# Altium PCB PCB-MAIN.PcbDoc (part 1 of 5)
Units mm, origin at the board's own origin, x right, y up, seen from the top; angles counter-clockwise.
Board outline 110 x 75 mm, 8 copper layers (F.Cu, In1.Cu, In2.Cu, In3.Cu, In4.Cu, In5.Cu, In6.Cu, B.Cu); 251 components, 185 nets, 1143 pads, 853 vias.
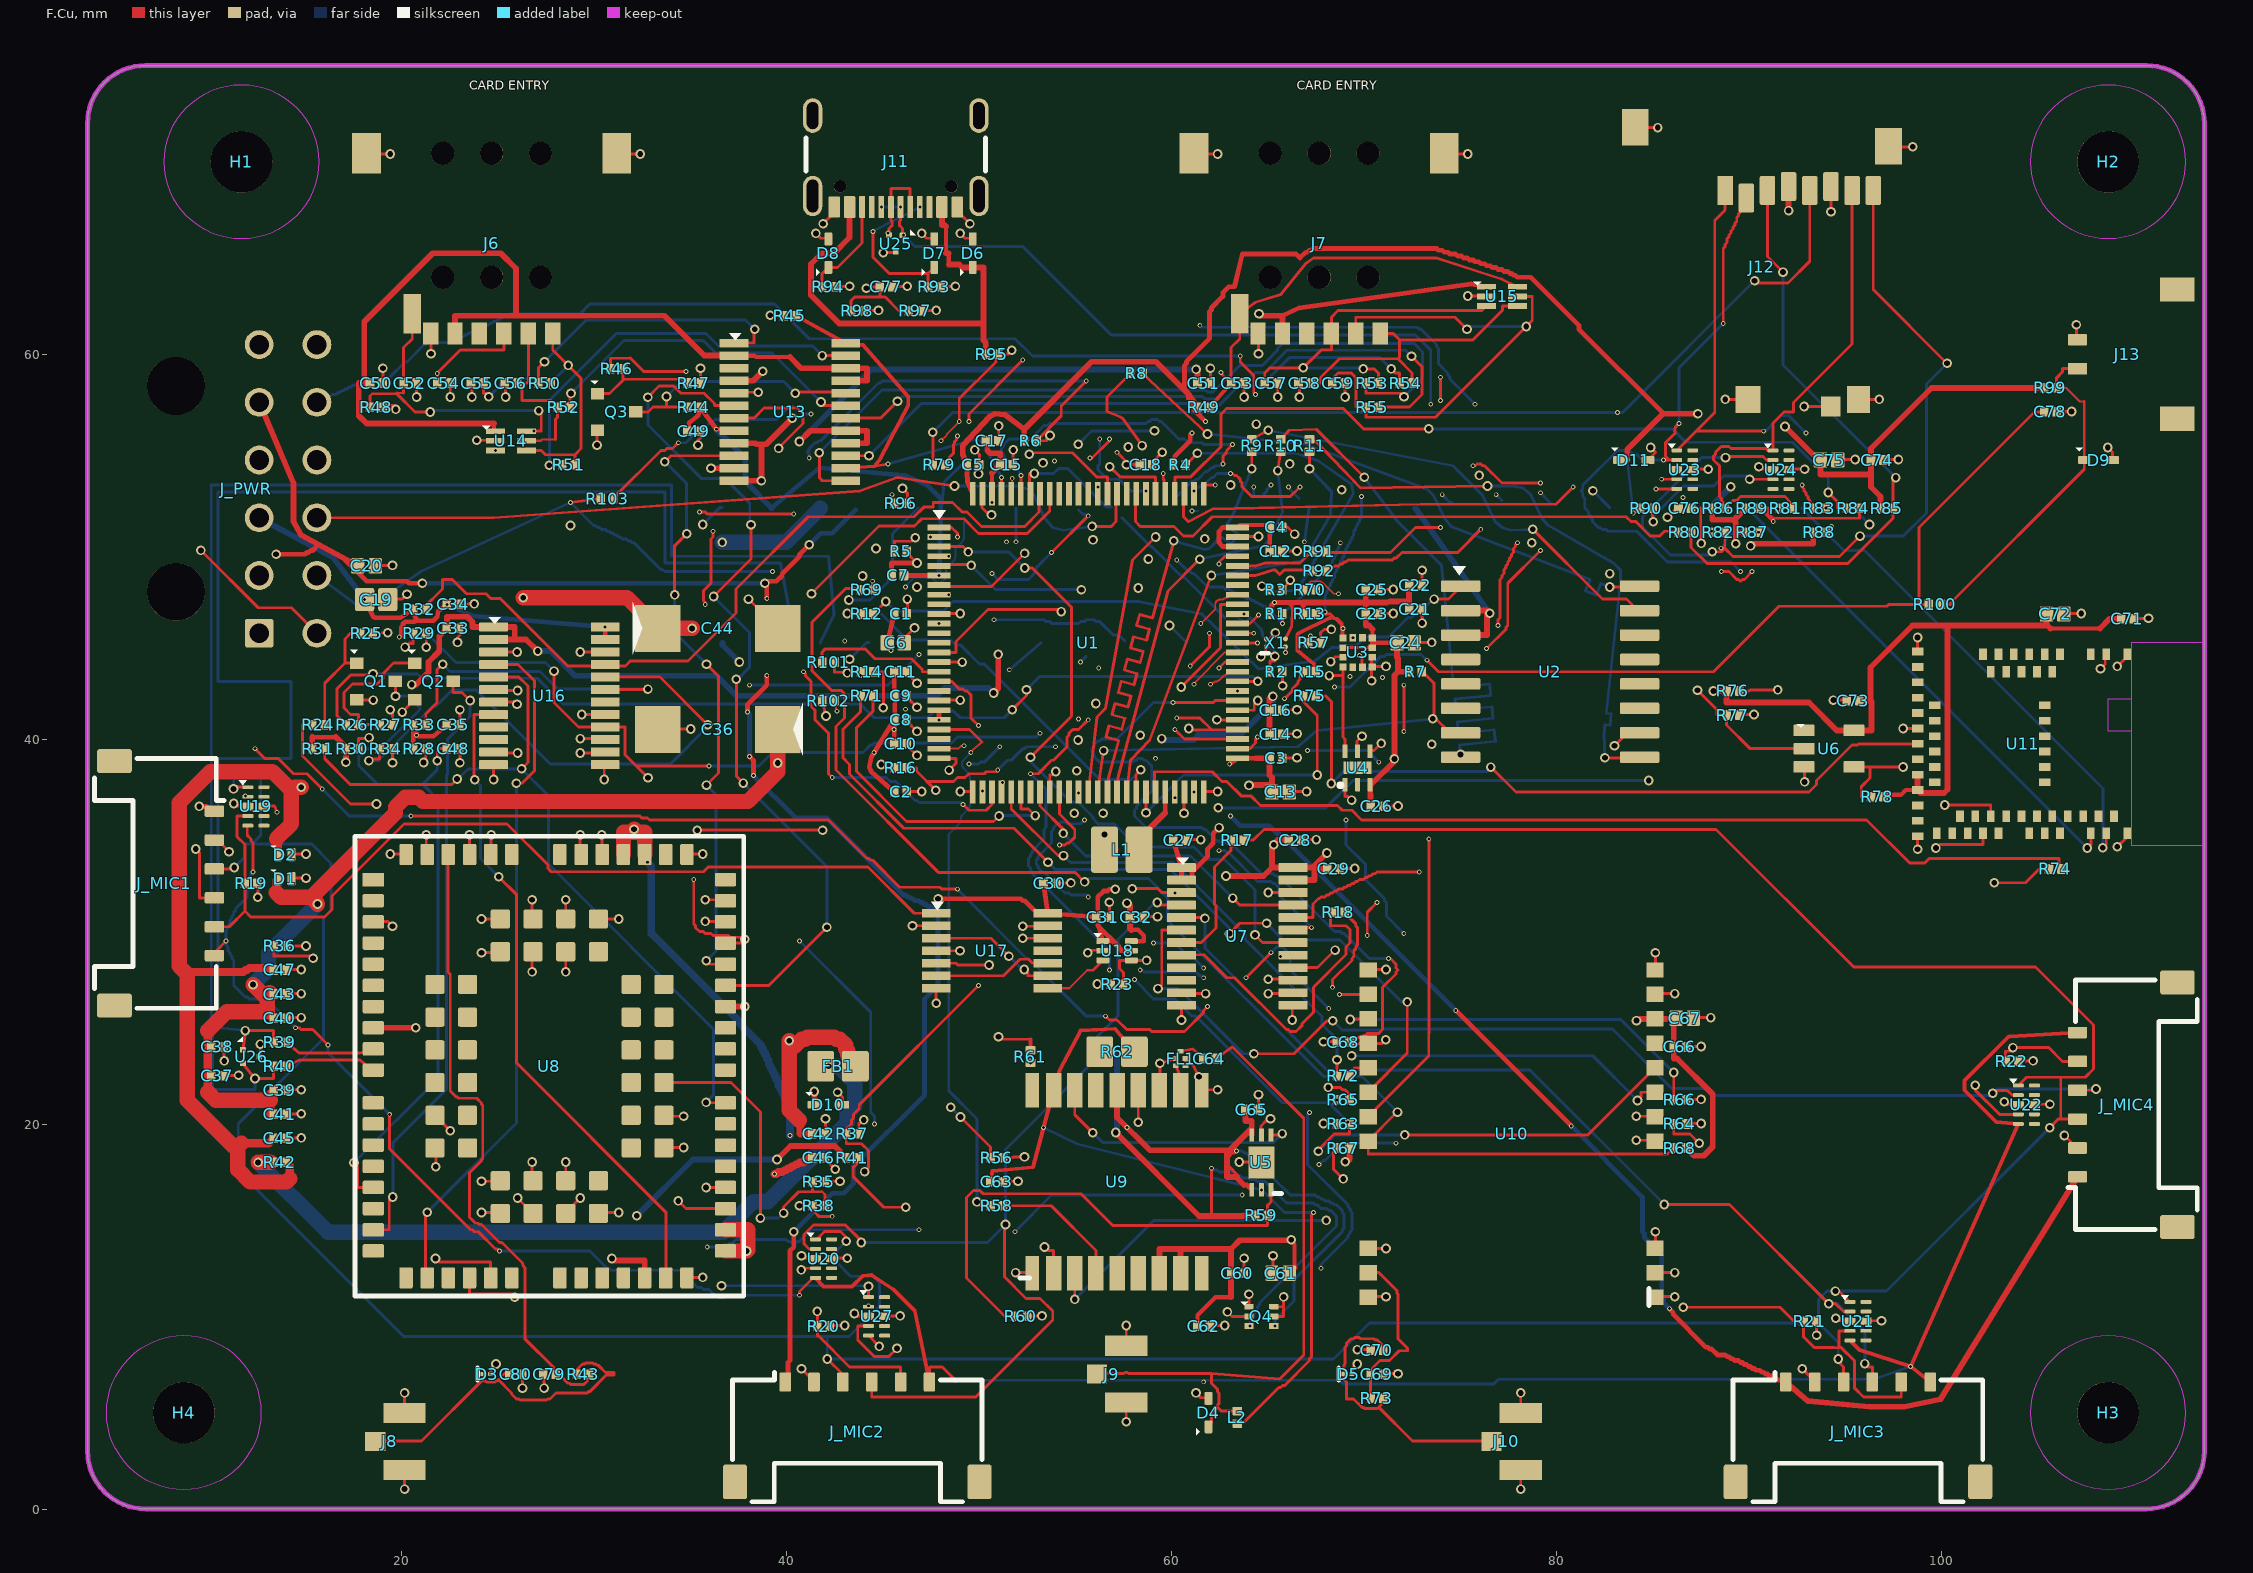
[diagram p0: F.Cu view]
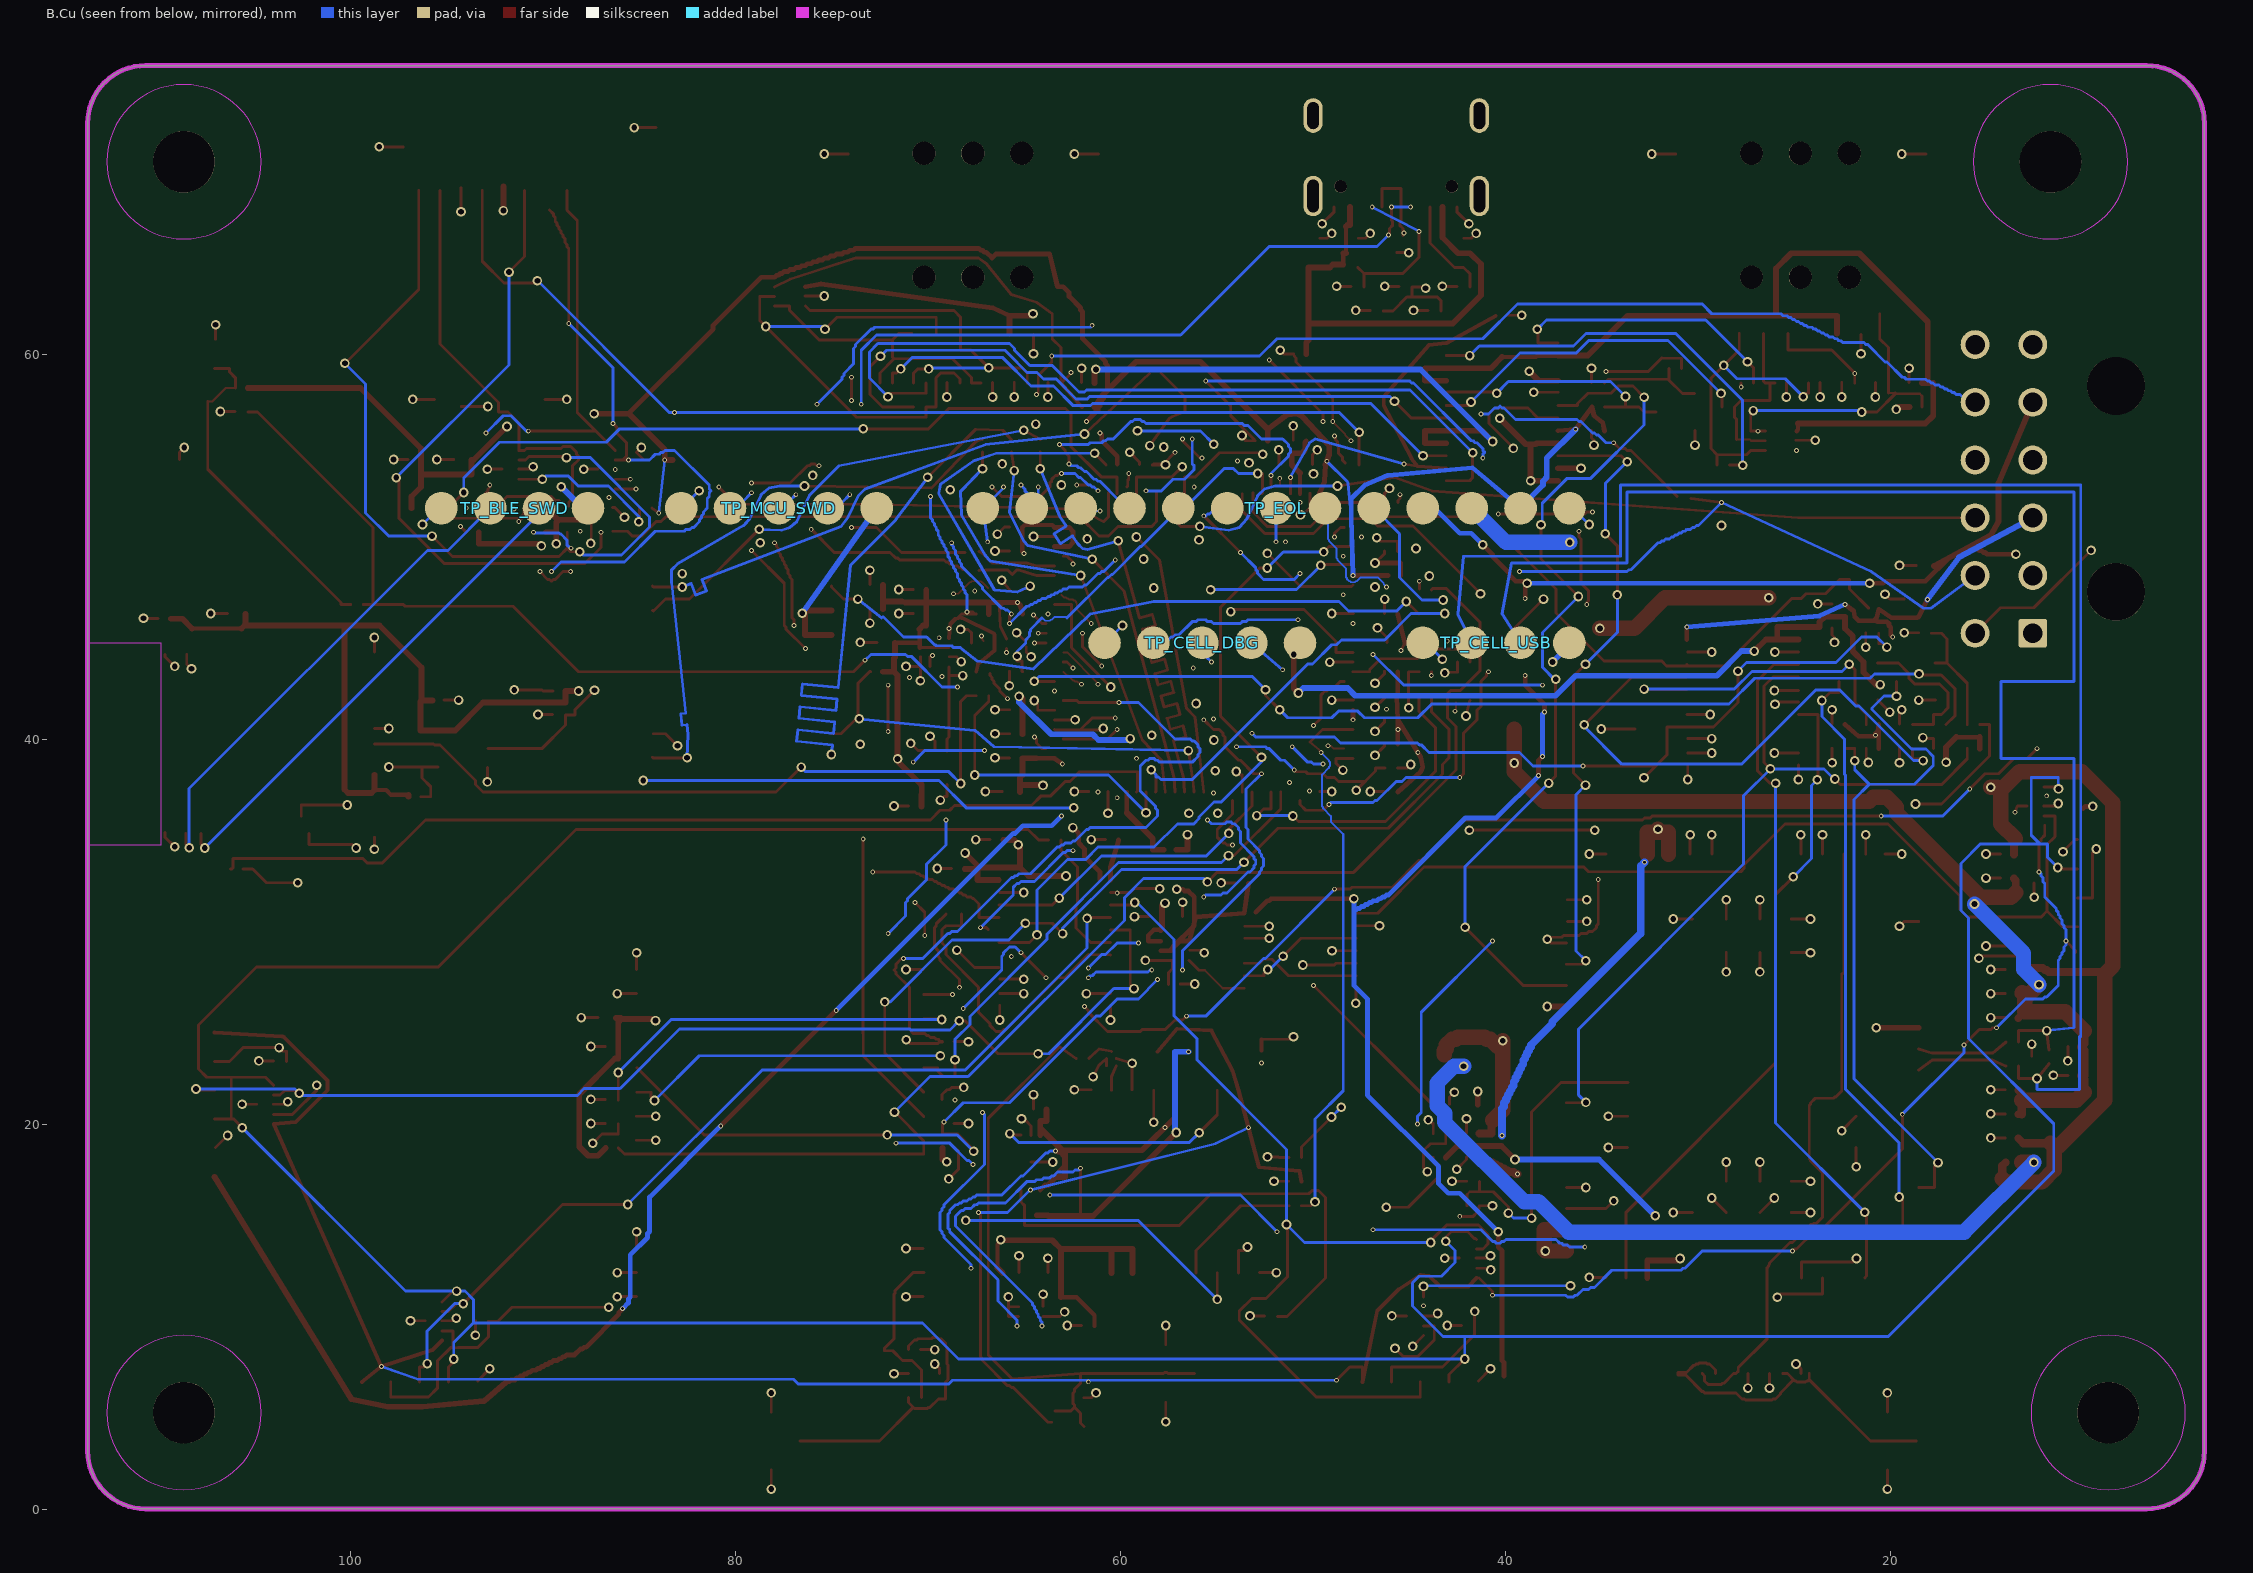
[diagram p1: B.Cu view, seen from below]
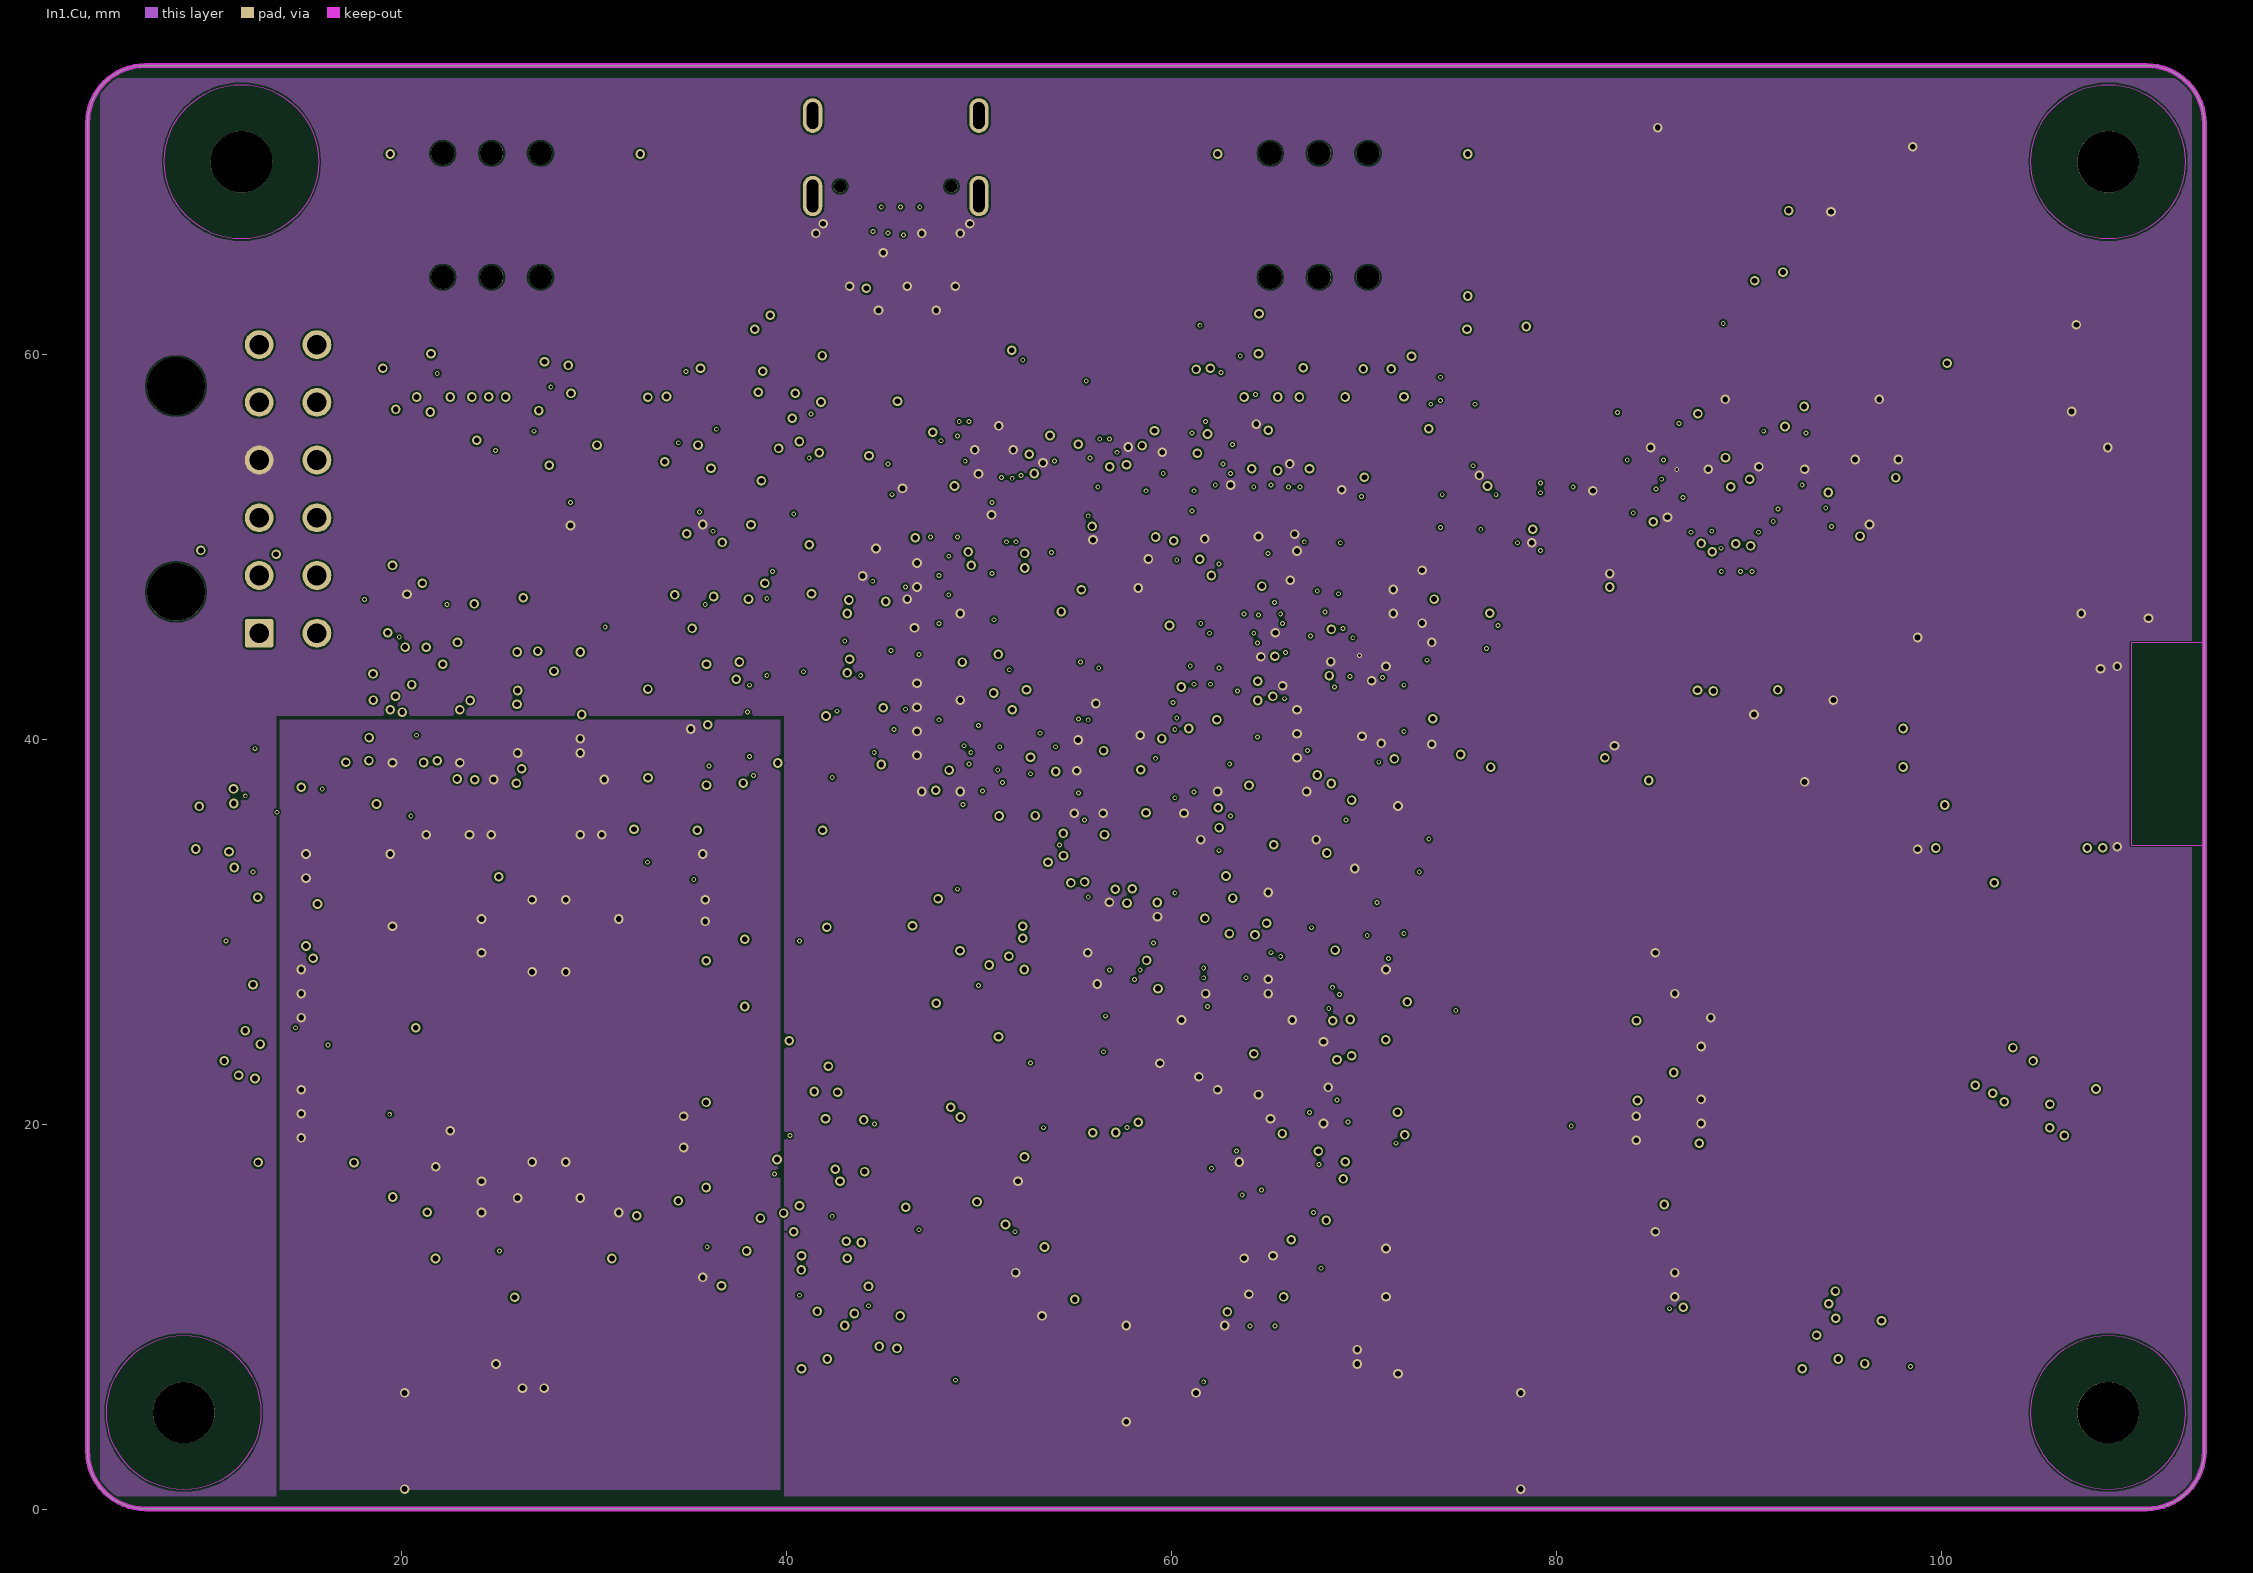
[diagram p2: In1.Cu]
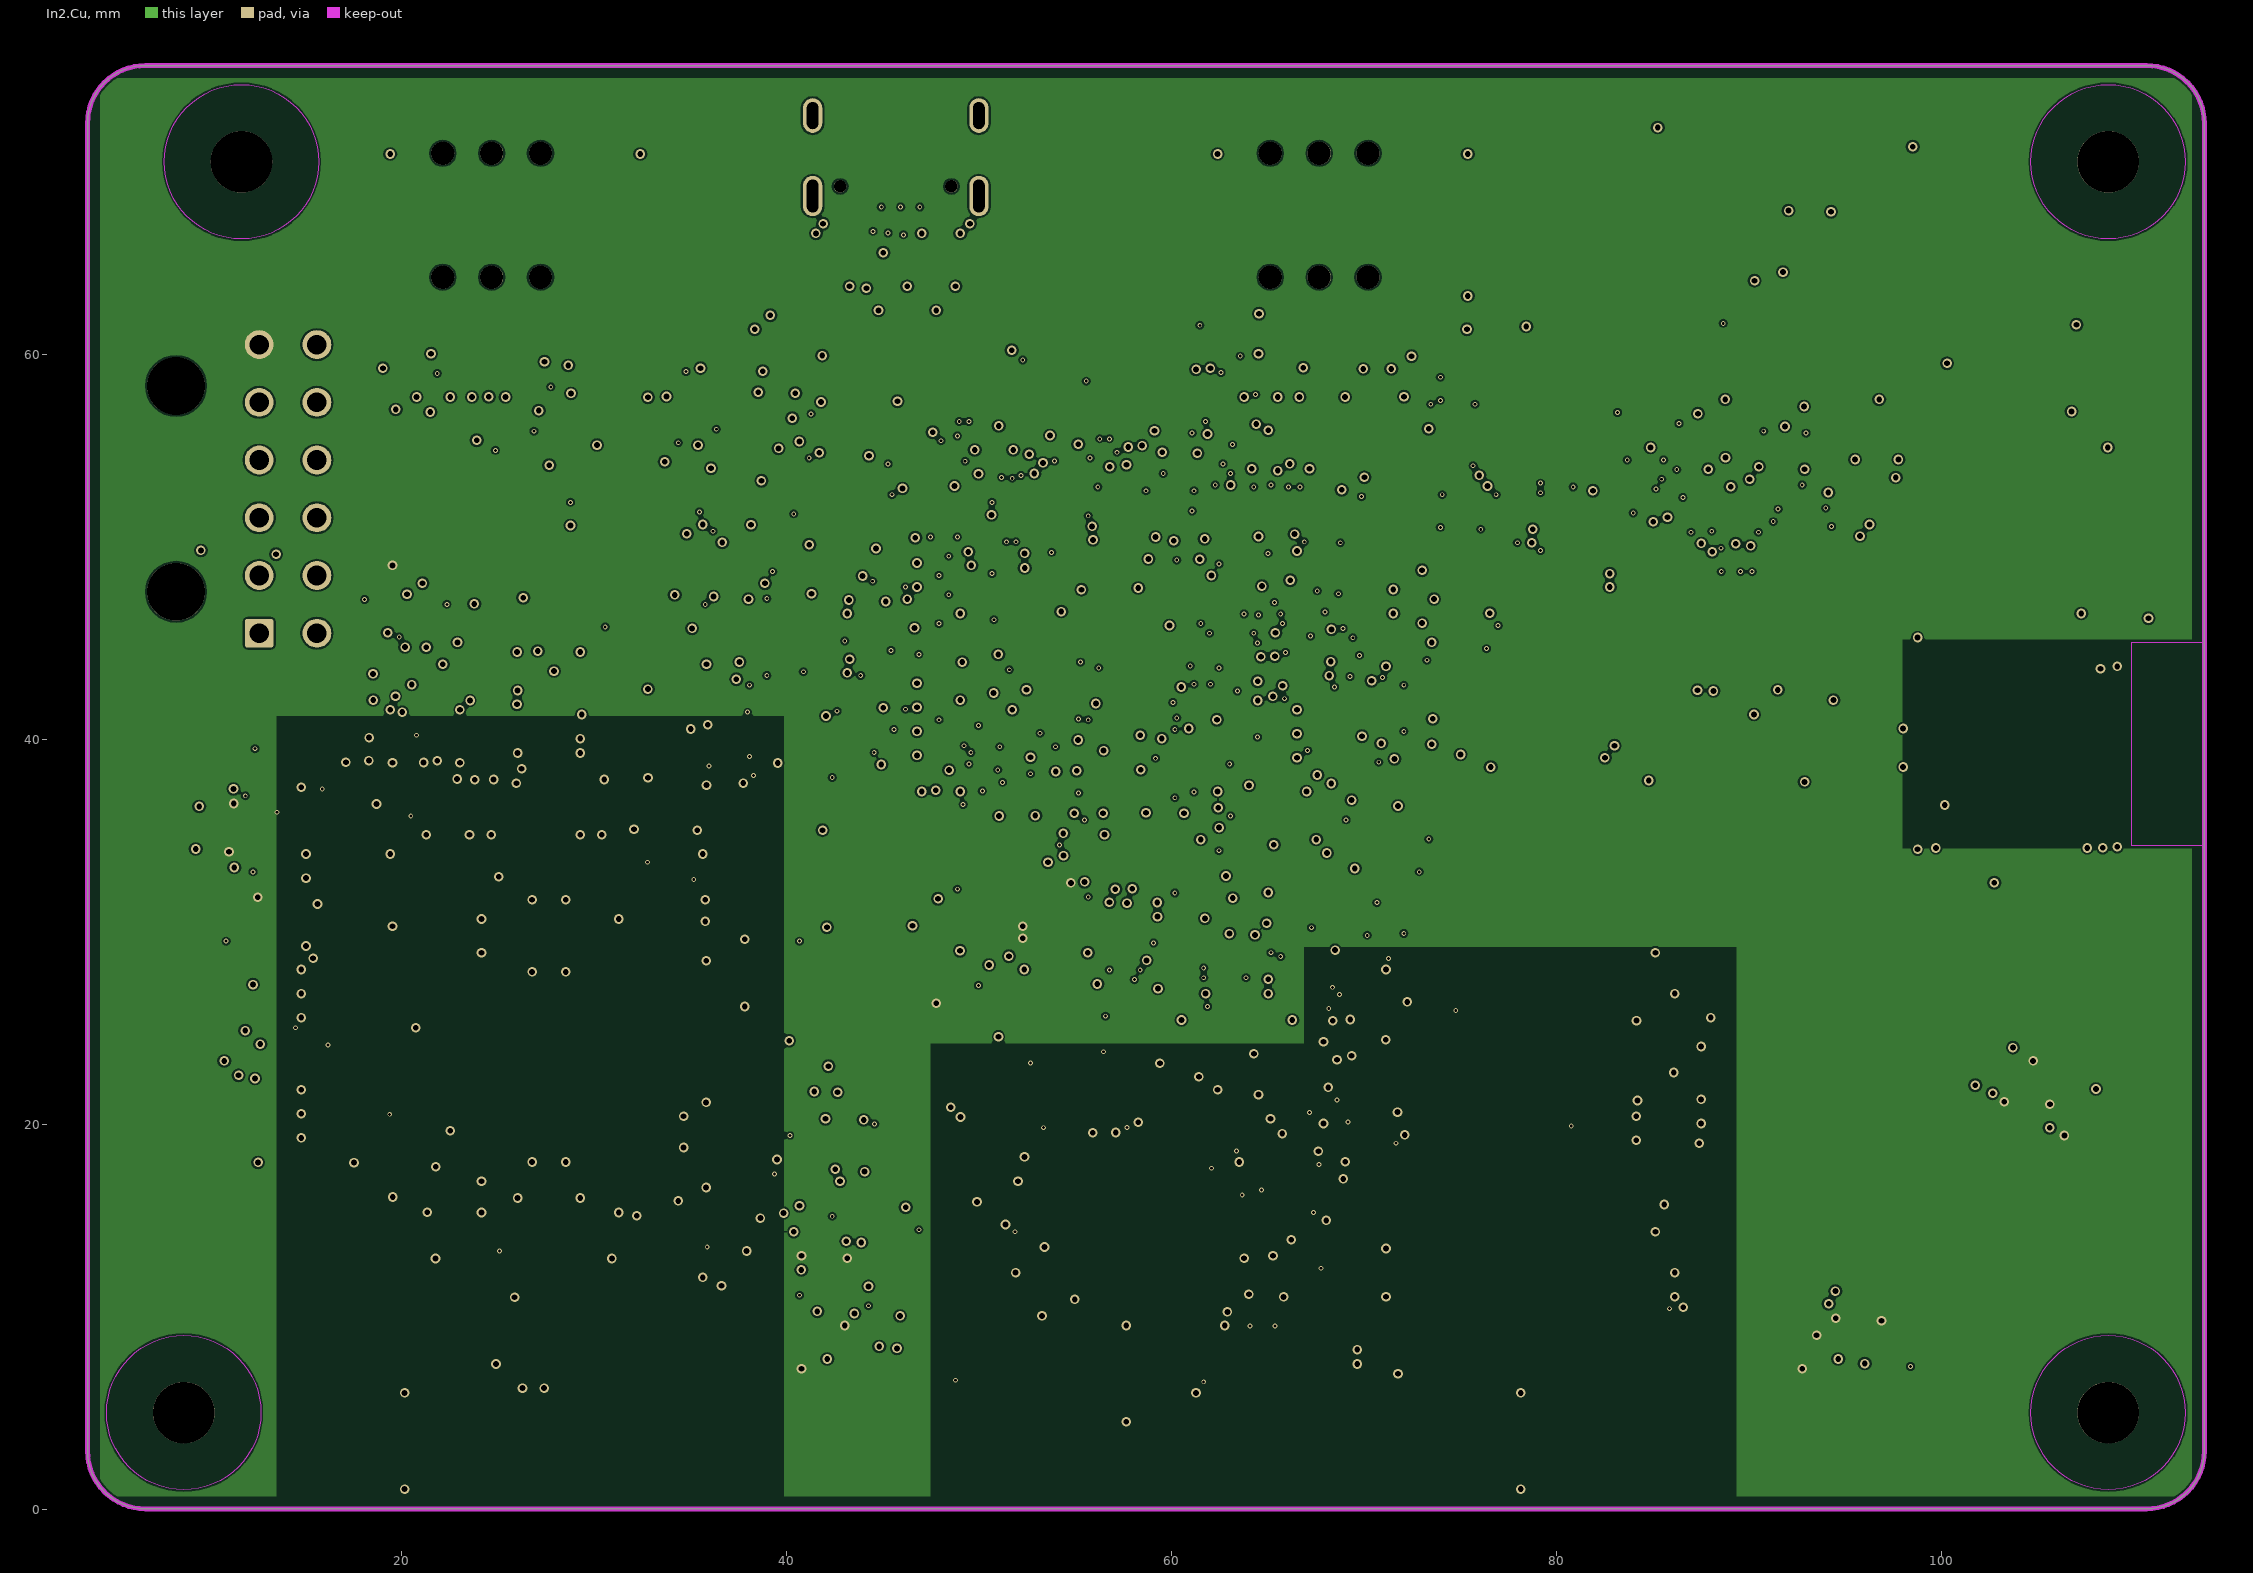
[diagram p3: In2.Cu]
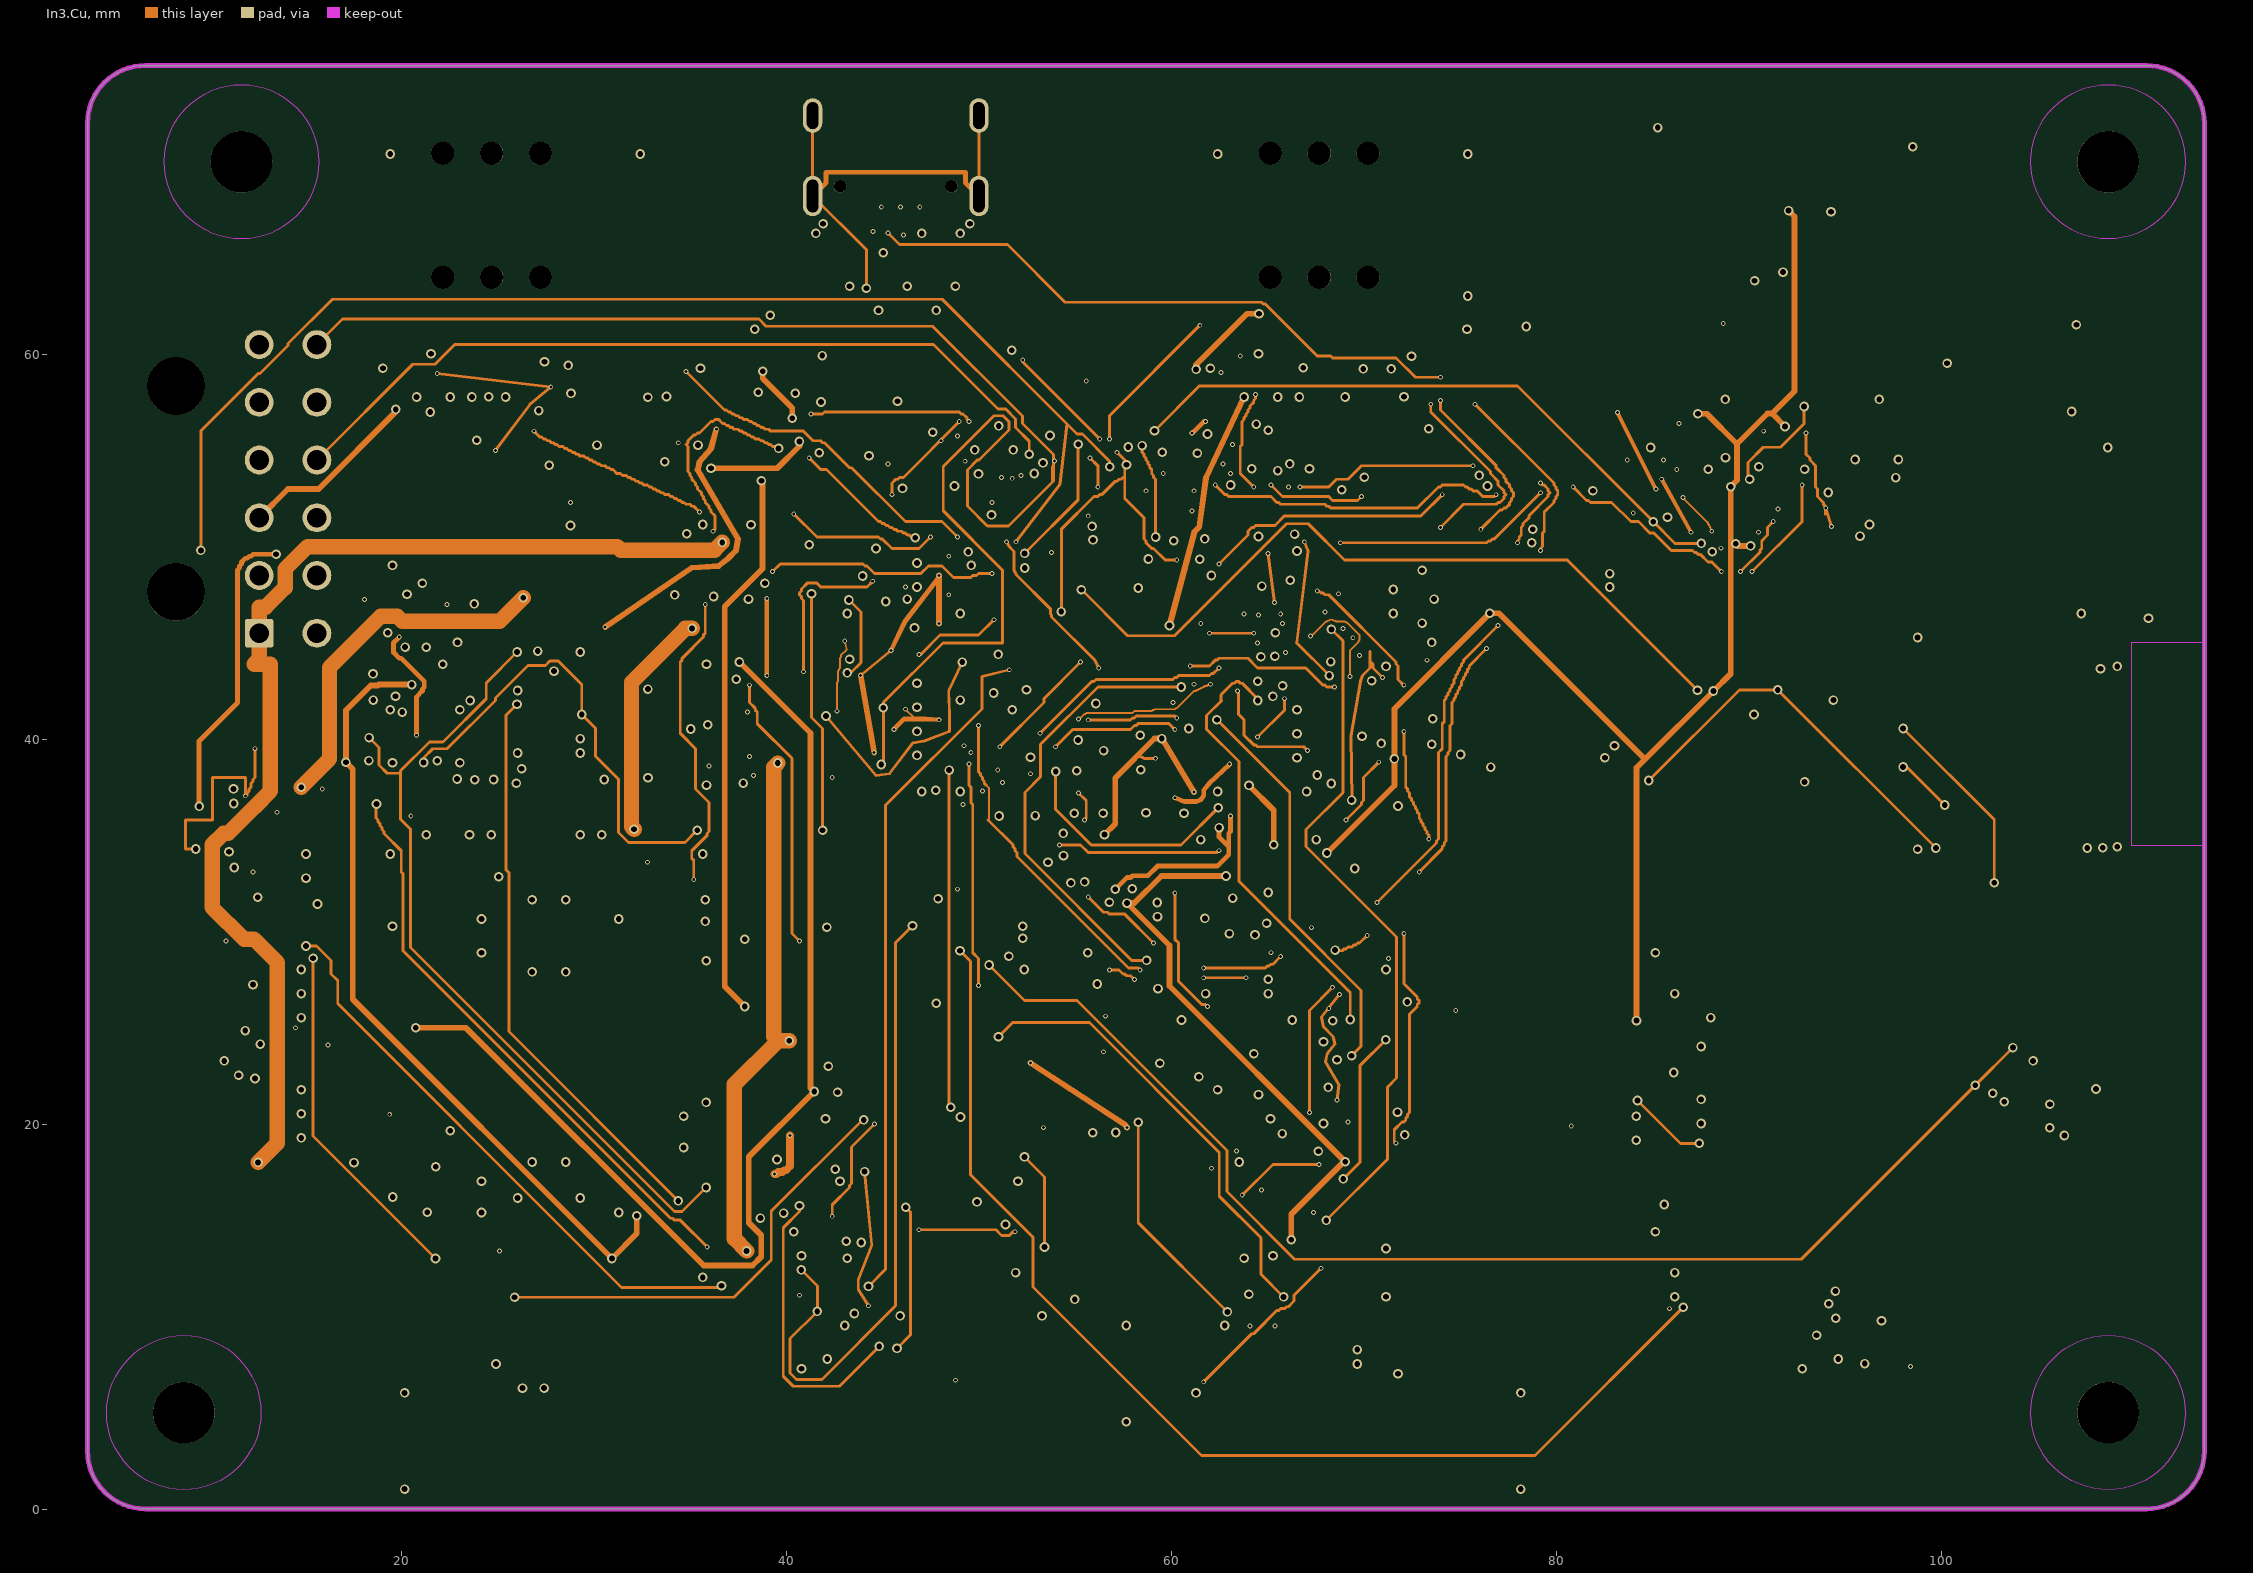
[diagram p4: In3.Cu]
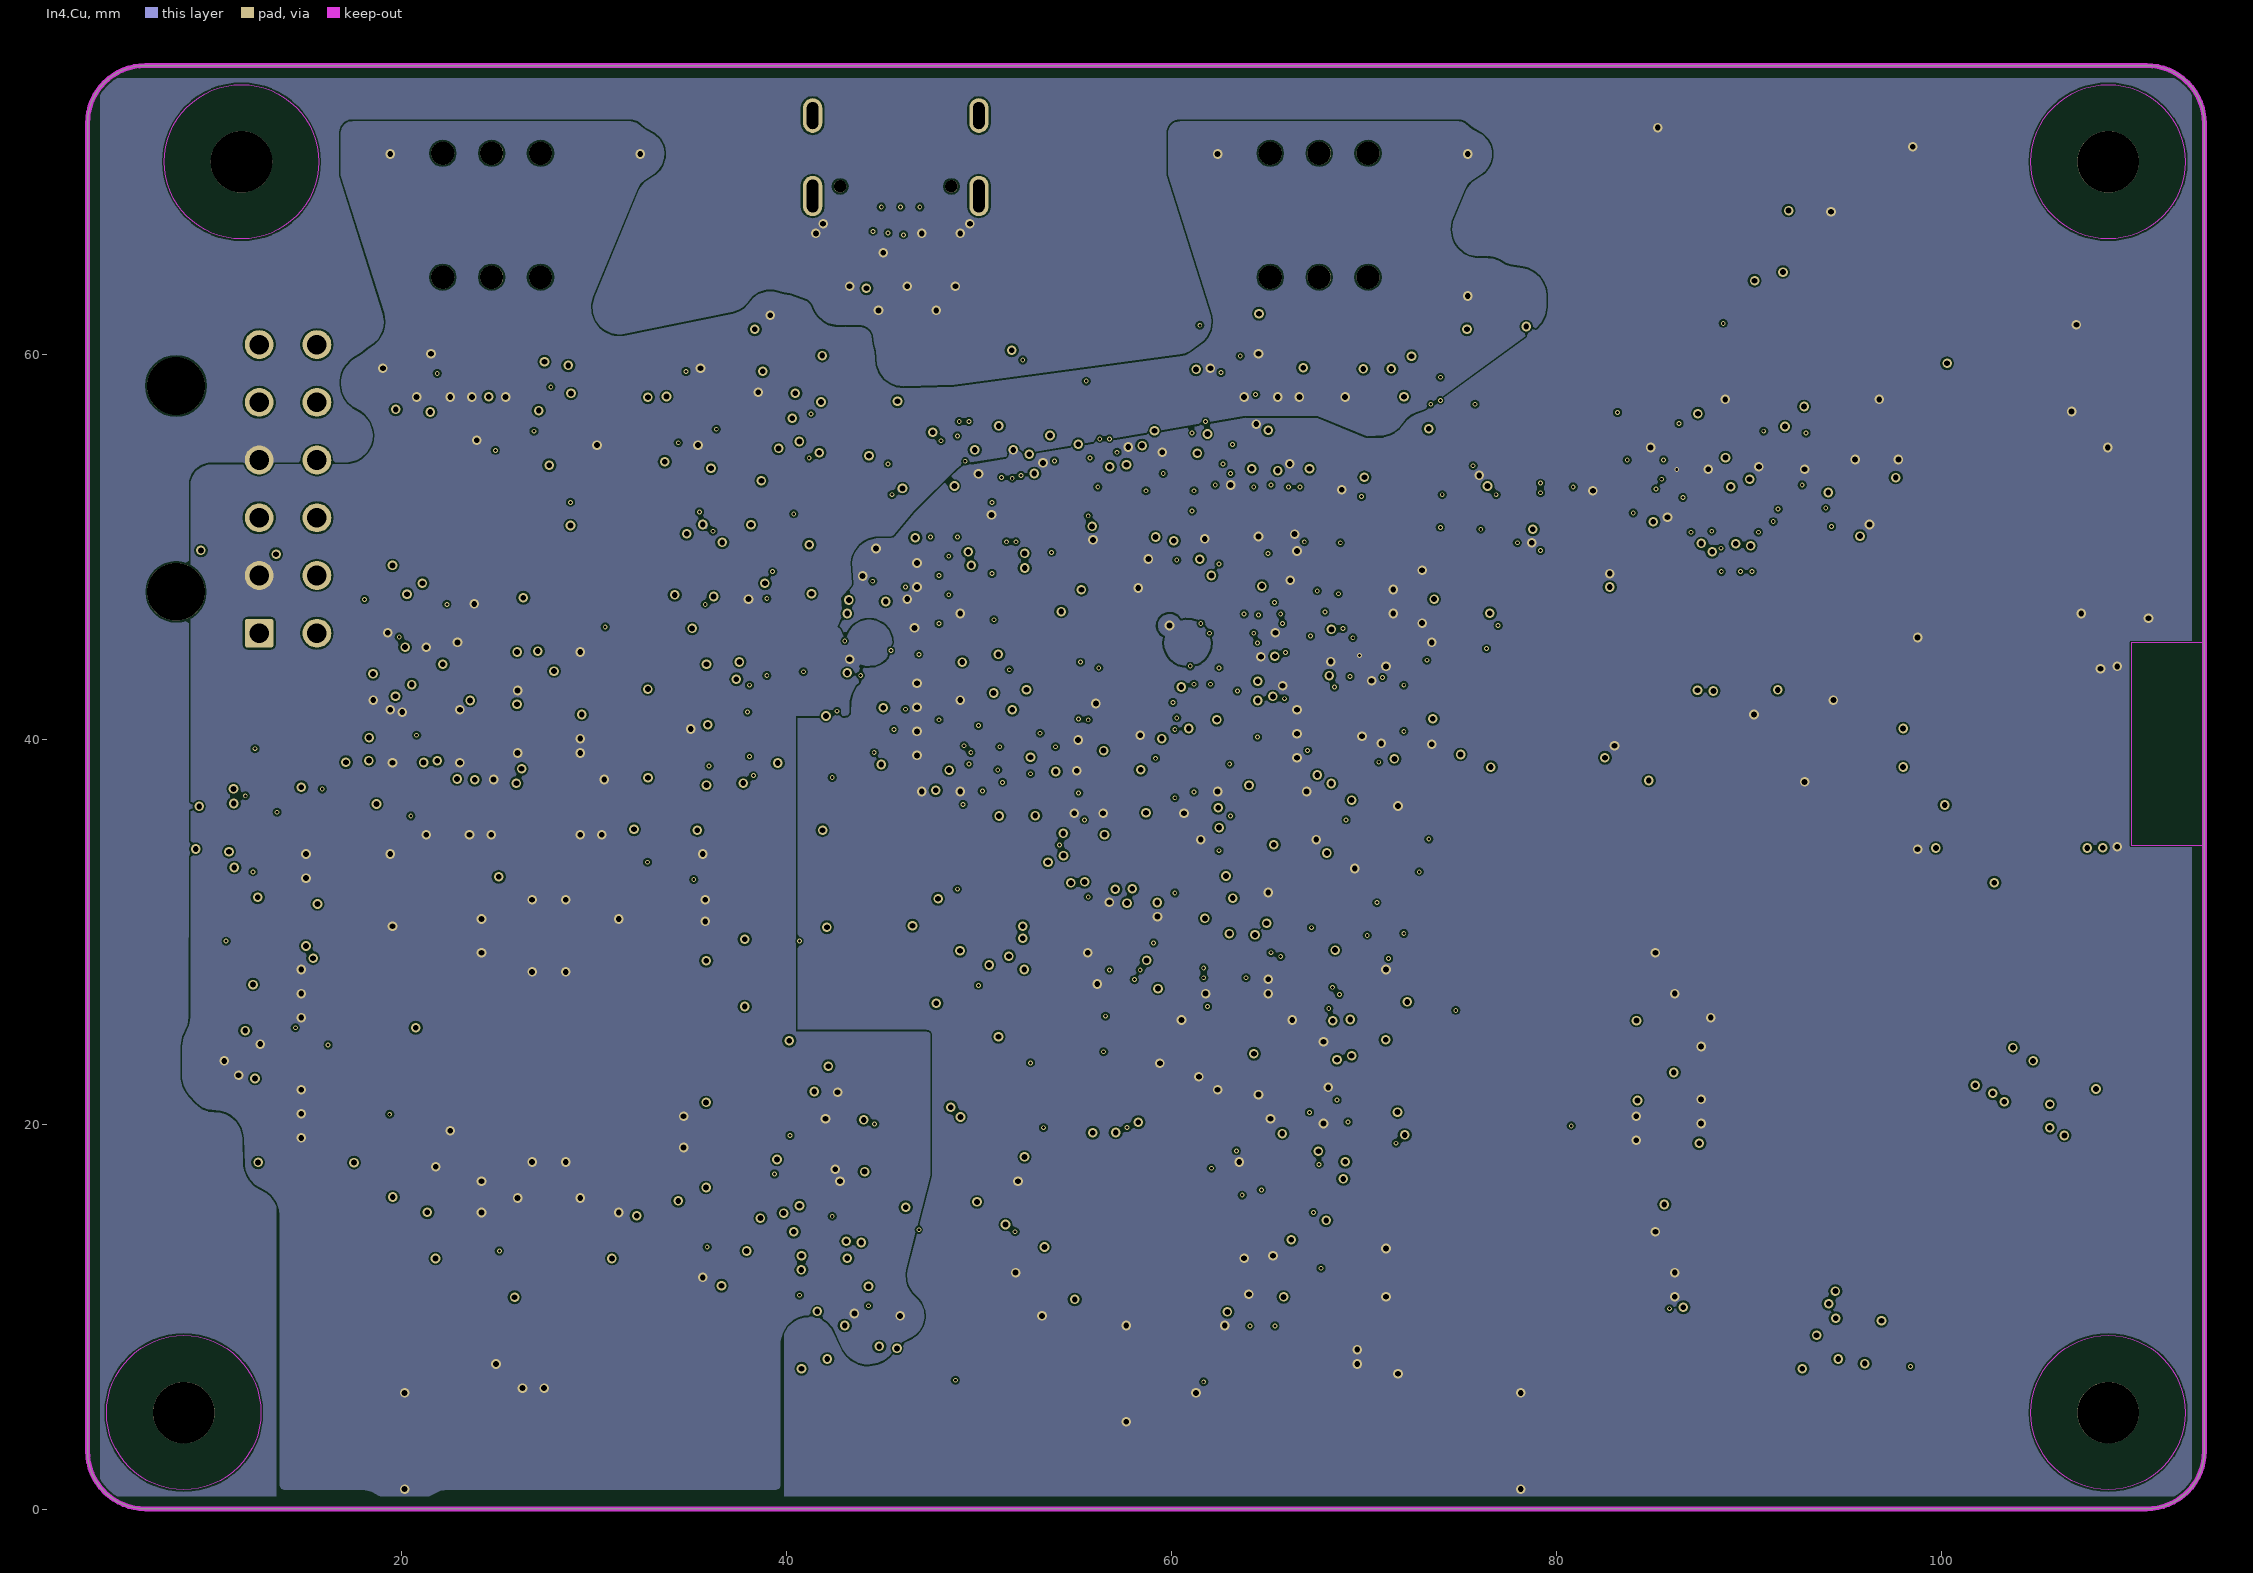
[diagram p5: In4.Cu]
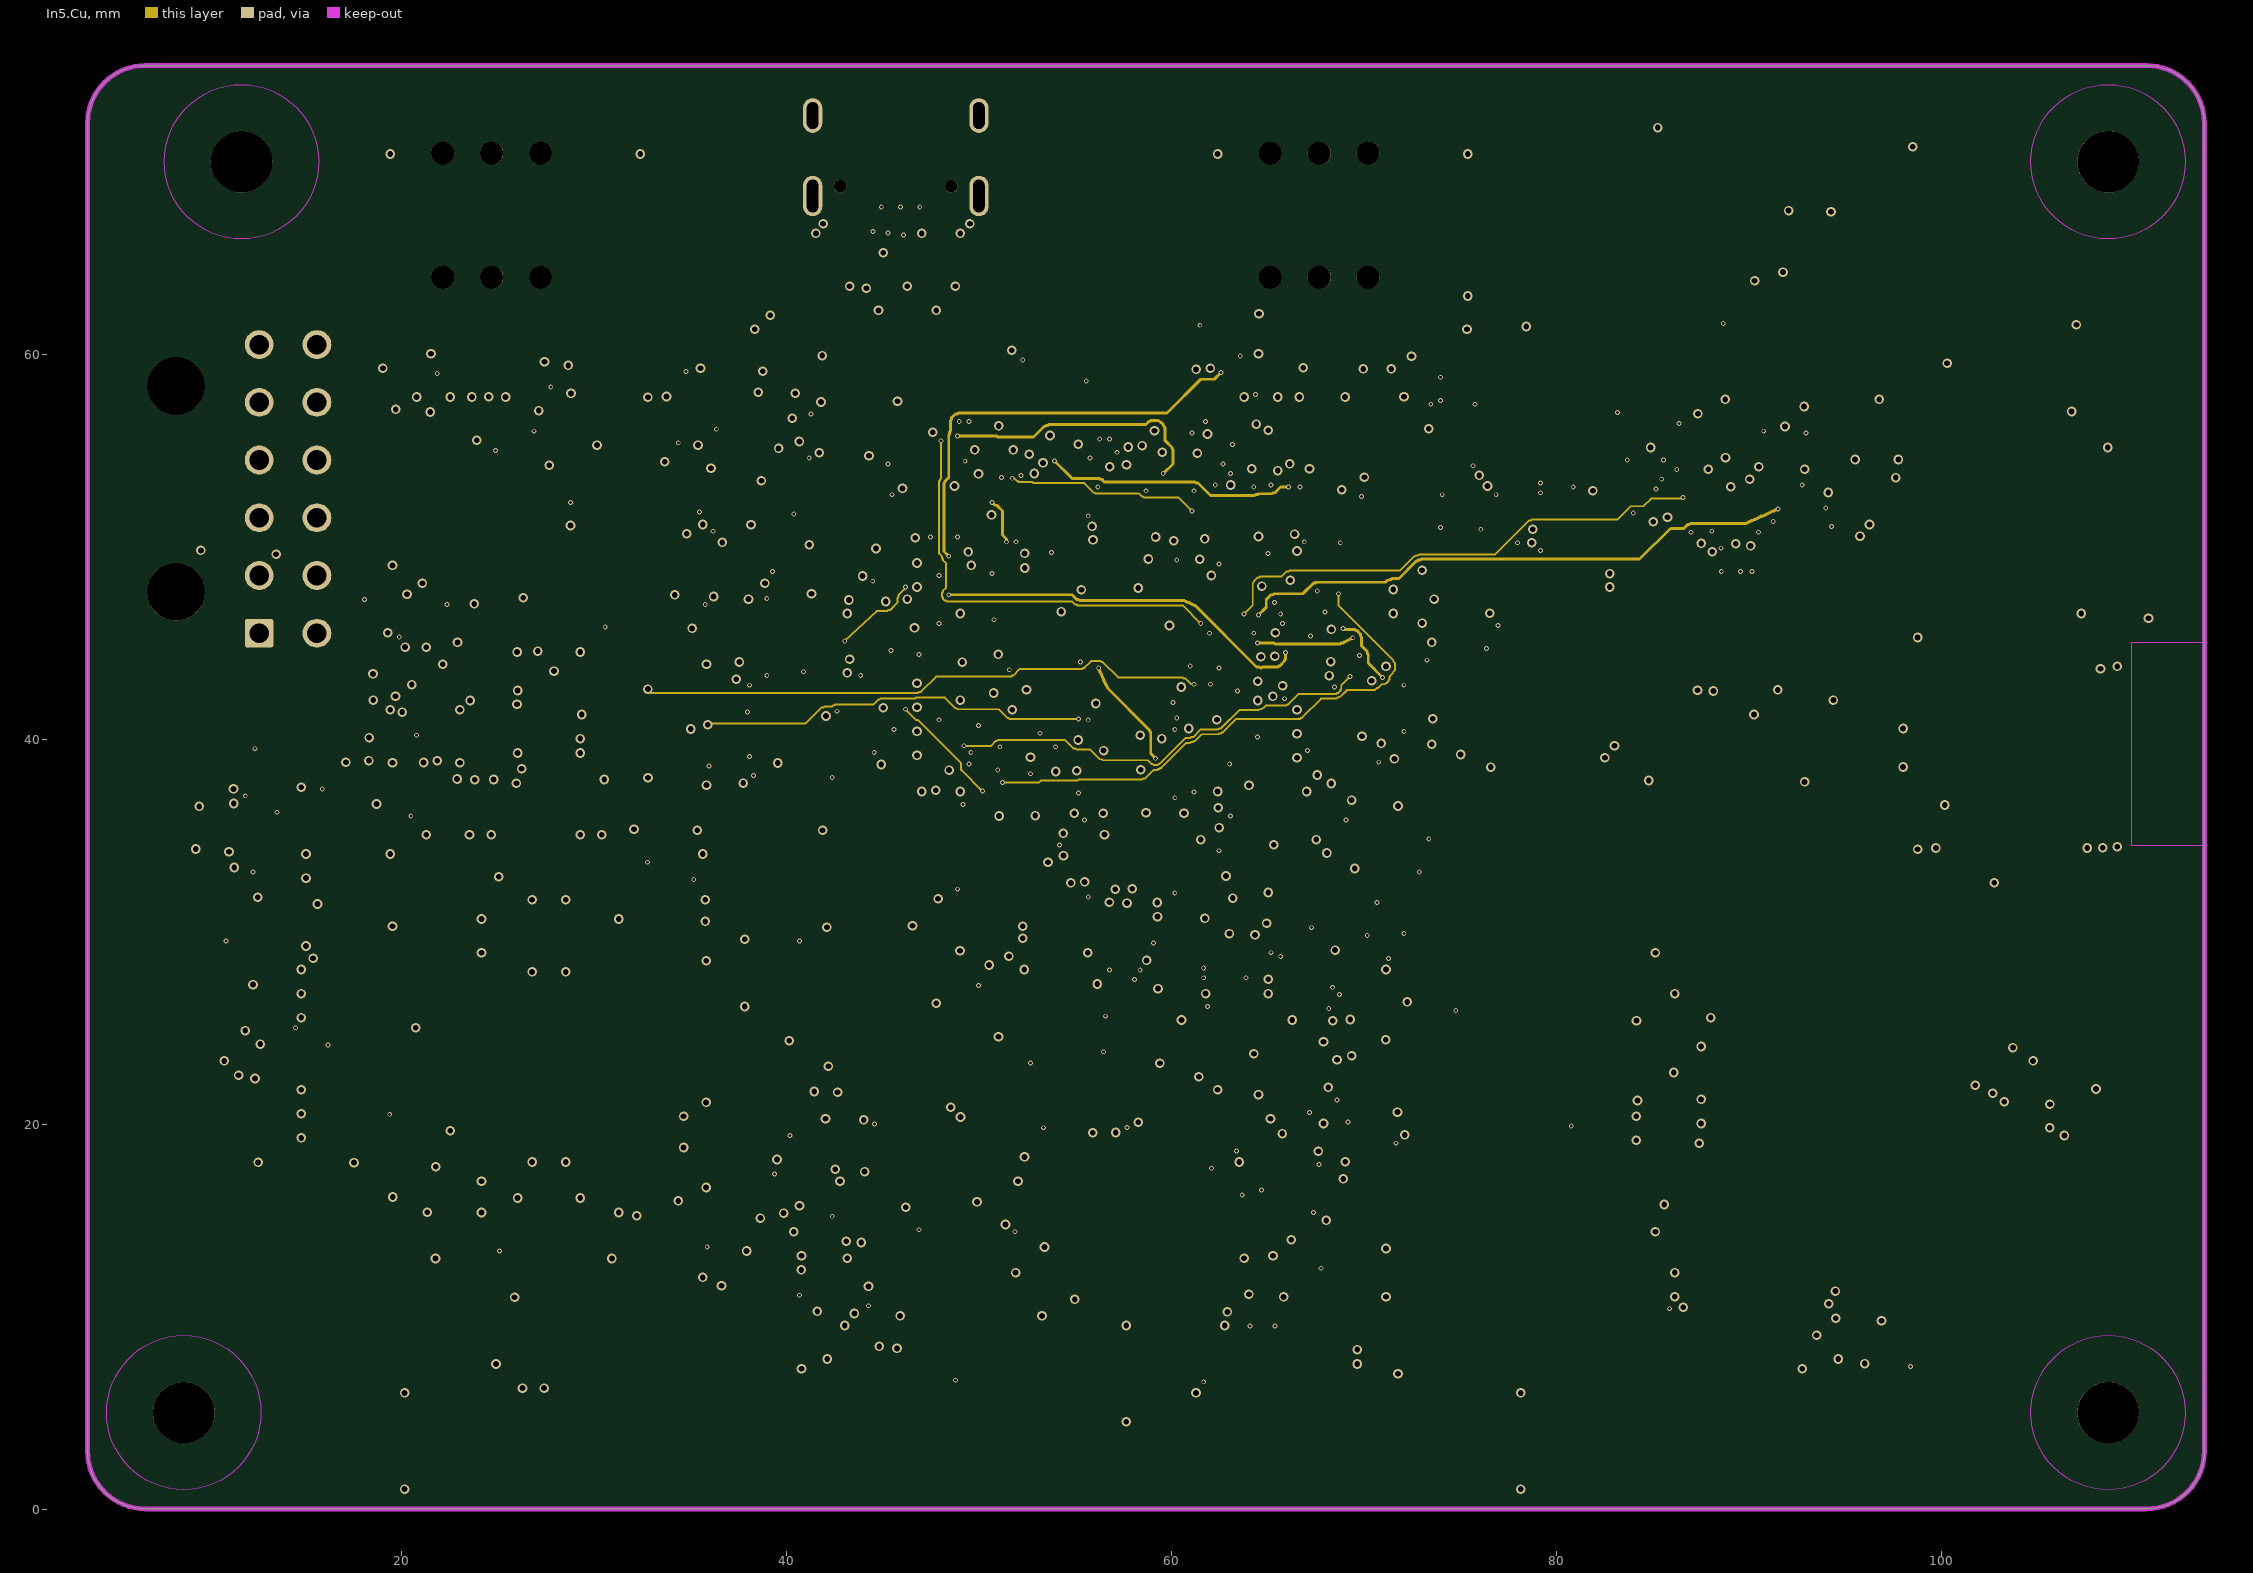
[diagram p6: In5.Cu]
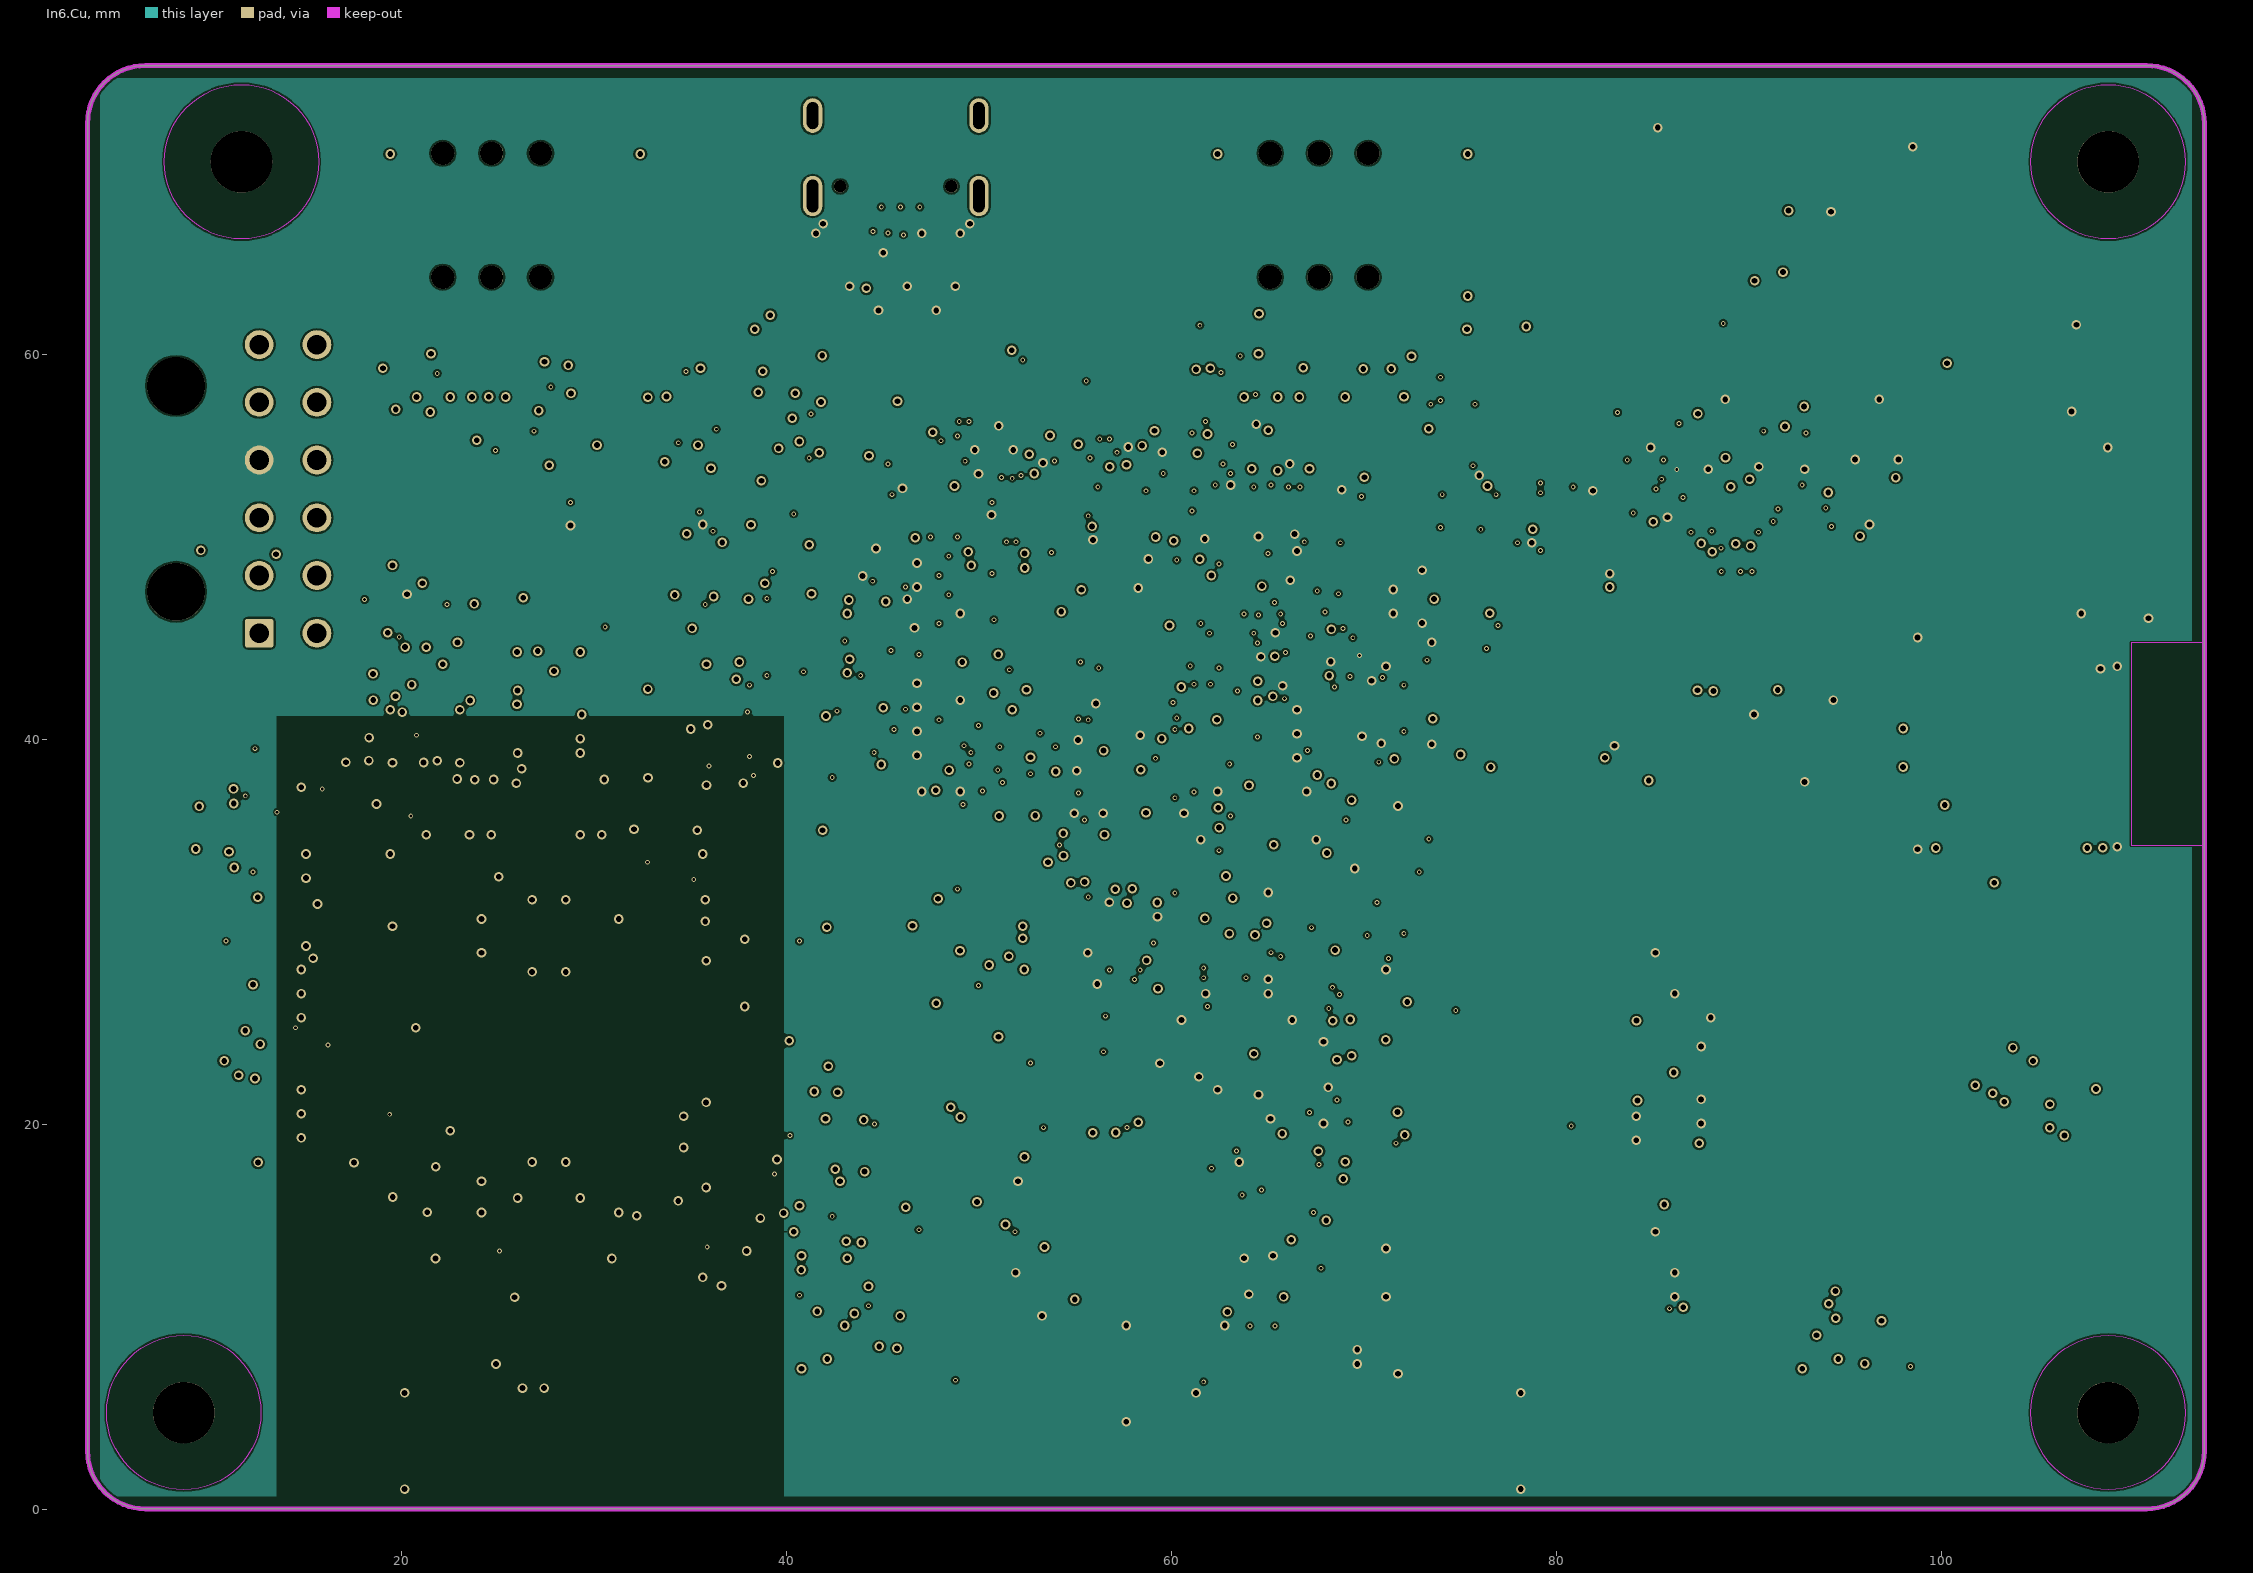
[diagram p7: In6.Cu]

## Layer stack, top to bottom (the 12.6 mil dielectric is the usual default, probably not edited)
F.Mask: solder mask 0.0102, Solder Resist, Dk 3.5
F.Cu: signal copper 0.0356
Dielectric 1: dielectric 0.32, FR-4, Dk 4.8
In1.Cu: signal copper 0.0356
Dielectric2: dielectric 0.32, FR-4, Dk 4.8
In2.Cu: signal copper 0.0356
Dielectric3: dielectric 0.32, FR-4, Dk 4.8
In3.Cu: signal copper 0.0356
Dielectric4: dielectric 0.32, FR-4, Dk 4.8
In4.Cu: signal copper 0.0356
Dielectric5: dielectric 0.32, FR-4, Dk 4.8
In5.Cu: signal copper 0.0356
Dielectric6: dielectric 0.32, FR-4, Dk 4.8
In6.Cu: signal copper 0.0356
Dielectric7: dielectric 0.32, FR-4, Dk 4.8
B.Cu: signal copper 0.0356
B.Mask: solder mask 0.0102, Solder Resist, Dk 3.5

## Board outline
110.685,0.025 6.685,0.025 cw(c6.686,3.026) 3.685,3.025 3.685,72.025 cw(c6.686,72.024) 110.685,75.025 cw(c110.684,72.024) 113.685,3.025 cw(c110.684,3.026) 110.685,0.025

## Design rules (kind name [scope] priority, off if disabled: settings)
Clearance "Clearence 0,18_PadClass" [InPadClass('Pad Class Clearance 0,18')] p1: gap=0.18 ignorepadtopadclearanceinfootprint=FALSE
Clearance "Clearence 0,12_PadClass" [InPadClass('Pad Class Clearance 0,12')] p2: gap=0.12 ignorepadtopadclearanceinfootprint=FALSE
Clearance "Clearence 0,1_Polygon" [InNamedPolygon('In1.Cu-GND_DIGITAL') OR InNamedPolygon('In1.Cu-GND_MODEM') OR InNamedPolygon('In2.Cu-GND_MIC') OR InNamedPolygon('In4.Cu-GND_MODEM') OR InNamedPolygon('In4.Cu-GND_MODEM-1') OR InNamedPolygon('In4.Cu-GND_DIGITAL') OR InNamedPolygon('In6.Cu-GND_DIGITAL')] p3: gap=0.1 ignorepadtopadclearanceinfootprint=FALSE
Clearance "Clearence 0,1_PadClass" [InPadClass('Pad Class Clearance 0,1')] p4: gap=0.1 ignorepadtopadclearanceinfootprint=FALSE
Clearance "Clearence 0,05_PadClass" [InPadClass('Pad Class Clearance 0,05')] p5: gap=0.05 ignorepadtopadclearanceinfootprint=FALSE
HoleSize [All] p1: absolutevalues=TRUE maxlimit=3.2 minlimit=0.025 maxpercent=80.000 minpercent=20.000
MinimumSolderMaskSliver [All] p1: minsoldermaskwidth=0
PolygonConnect Polygon_In6.Cu-GND_DIGITAL_ConnectDirect [IsNamedPolygon('In6.Cu-GND_DIGITAL')] p1: connectstyle=Direct reliefconductorwidth=0.254 reliefentries=4 polygonreliefangle="90 Angle" airgapwidth=0.254
PolygonConnect Polygon_In4.Cu-GND_DIGITAL_ConnectDirect [IsNamedPolygon('In4.Cu-GND_DIGITAL')] p2: connectstyle=Direct reliefconductorwidth=0.254 reliefentries=4 polygonreliefangle="90 Angle" airgapwidth=0.254
PolygonConnect Polygon_In4.Cu-GND_MODEM-1_ConnectDirect [IsNamedPolygon('In4.Cu-GND_MODEM-1')] p3: connectstyle=Direct reliefconductorwidth=0.254 reliefentries=4 polygonreliefangle="90 Angle" airgapwidth=0.254
PolygonConnect Polygon_In4.Cu-GND_MODEM_ConnectDirect [IsNamedPolygon('In4.Cu-GND_MODEM')] p4: connectstyle=Direct reliefconductorwidth=0.254 reliefentries=4 polygonreliefangle="90 Angle" airgapwidth=0.254
PolygonConnect Polygon_In2.Cu-GND_MIC_ConnectDirect [IsNamedPolygon('In2.Cu-GND_MIC')] p5: connectstyle=Direct reliefconductorwidth=0.254 reliefentries=4 polygonreliefangle="90 Angle" airgapwidth=0.254
PolygonConnect Polygon_In1.Cu-GND_MODEM_ConnectDirect [IsNamedPolygon('In1.Cu-GND_MODEM')] p6: connectstyle=Direct reliefconductorwidth=0.254 reliefentries=4 polygonreliefangle="90 Angle" airgapwidth=0.254
PolygonConnect Polygon_In1.Cu-GND_DIGITAL_ConnectDirect [IsNamedPolygon('In1.Cu-GND_DIGITAL')] p7: connectstyle=Direct reliefconductorwidth=0.254 reliefentries=4 polygonreliefangle="90 Angle" airgapwidth=0.254
RoutingVias [All] p1: holewidth=0.711 width=1.27 viastyle="Through Hole" minholewidth=0.711 minwidth=1.27 maxholewidth=0.711 maxwidth=1.27
SilkToSilkClearance [All] p1: silktosilkclearance=0
SilkToSolderMaskClearance [IsPad] p1: minsilkscreentomaskgap=0 clearancetoexposedcopper=TRUE
SolderMaskExpansion [All] p1: expansion=0 istentingtop=FALSE
Width [All] p1: maxlimit=10 minlimit=0.1 preferedwidth=0.254 minimp=50.000000 maximp=50.000000 favimp=50.000000
26 further rules are at their usual default settings.

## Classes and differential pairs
pad class "Pad Class Clearance 0,18": U4-1 U4-2 U4-3 U4-4 U4-5 U4-6 U4-EP
pad class "Pad Class Clearance 0,12": U3-1 U3-2 U3-3 U3-4 U3-5 U3-6 U3-7 U3-8 U3-9 U3-10 U3-11 U3-12 X1-1 X1-2 X1-3 X1-4
pad class "Pad Class Clearance 0,1": D3-1 D3-2 D5-1 D5-2
pad class "Pad Class Clearance 0,05": FL1-A FL1-B FL1-C FL1-D FL1-E J6-1 J6-2 J6-3 J6-4 J6-5 J6-6 J6-7 J6-SHIELD J6-Un1 J6-Un2 J6-Un3 J6-Un4 J6-Un5 J6-Un6 J7-1 J7-2 J7-3 J7-4 J7-5 J7-6 J7-7 J7-SHIELD J7-Un1 J7-Un2 J7-Un3 J7-Un4 J7-Un5 J7-Un6

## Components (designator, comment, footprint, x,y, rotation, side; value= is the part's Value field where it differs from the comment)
C1 "Comment" ?#1 45.935,46.525 r0 top value=GRM155R71E104KE14D
C2 "Comment" ?#1 45.935,37.275 r0 top value=GRM155R71E104KE14D
C3 "Comment" ?#1 65.435,39.025 r0 top value=GRM155R71E104KE14D
C4 "Comment" ?#1 65.435,51.025 r0 top value=GRM155R71E104KE14D
C5 "Comment" ?#1 49.685,54.275 r0 top value=GRM155R71E104KE14D
C6 "Comment" ?#2 45.685,45.025 r0 top value=GRM188R61A106KE69D
C7 "Comment" ?#1 45.785,48.525 r180 top value=GRM155R71E104KE14D
C8 "Comment" ?#1 45.935,41.025 r0 top value=GRM155R71E104KE14D
C9 "Comment" ?#1 45.935,42.275 r0 top value=GRM155R61C105KA12D
C10 "Comment" ?#1 45.935,39.775 r0 top value=GRM155R71E104KE14D
C11 "Comment" ?#1 45.935,43.525 r0 top value=GRM155R61C105KA12D
C12 "Comment" ?#1 65.435,49.775 r0 top value=GRM155R71E104KE14D
C13 "Comment" ?#2 65.685,37.275 r0 top value=GRM188R61A106KE69D
C14 "Comment" ?#1 65.435,40.275 r0 top value=GRM155R61A225KE15D
C15 "Comment" ?#1 51.435,54.275 r0 top value=GRM155R61A225KE15D
C16 "Comment" ?#1 65.435,41.525 r0 top value=GRM155R71E104KE14D
C17 "Comment" ?#1 50.685,55.525 r0 top value=GRM155R71E104KE14D
C18 "Comment" ?#1 58.685,54.275 r0 top value=GRM155R71E104KE14D
C19 "Comment" ?#3 18.685,47.275 r0 top value=GRM21BR61A226ME44L
C20 "Comment" ?#2 18.185,49.025 r0 top value=GRM188R61A106KE69D
C21 "Comment" ?#1 72.685,46.775 r0 top value=GRM155R71E104KE14D
C22 "Comment" ?#1 72.685,48.025 r0 top value=GRM155R61C105KA12D
C23 "Comment" ?#1 70.435,46.525 r0 top value=GRM155R71E104KE14D
C24 "Comment" ?#2 72.185,45.025 r0 top value=GRM188R61A106KE69D
C25 "Comment" ?#1 70.435,47.775 r0 top value=GRM155R71E104KE14D
C26 "Comment" ?#1 70.685,36.525 r0 top value=GRM155R71E104KE14D
C27 "Comment" ?#1 60.435,34.775 r0 top value=GRM155R71E104KE14D
C28 "Comment" ?#1 66.435,34.775 r0 top value=GRM155R71E104KE14D
C29 "Comment" ?#1 68.435,33.275 r0 top value=GRM155R71E104KE14D
C30 "Comment" ?#1 53.685,32.525 r0 top value=GRM155R71E104KE14D
C31 "Comment" ?#1 56.435,30.775 r0 top value=GRM155R71E104KE14D
C32 "Comment" ?#1 58.185,30.775 r0 top value=GRM155R71E104KE14D
C33 "Comment" ?#1 22.685,45.775 r0 top value=GRM155R71E104KE14D
C34 "Comment" ?#1 22.685,47.025 r0 top value=GRM155R71E104KE14D
C35 "Comment" ?#1 22.685,40.775 r0 top value=GRM155R71E104KE14D
C36 "Comment" KEMET_T52X_D_7343-31_DensityB 36.435,40.525 r180 top value=T520D107M006ATE015
C37 "Comment" ?#1 10.435,22.525 r0 top value=GRM155R71E224KE14D
C38 "Comment" ?#1 10.435,24.025 r0 top value=GRM155R71E473KA01D
C39 "Comment" ?#1 13.685,21.775 r0 top value=GRM1555C1H151JA01D
C40 "Comment" ?#1 13.685,25.525 r0 top value=GRM1555C1H101JA01D
C41 "Comment" ?#1 13.685,20.525 r0 top value=GRM1555C1H680JA01D
C42 "Comment" ?#1 41.685,19.525 r0 top value=GRM1555C1H330JA01D
C43 "Comment" ?#1 13.685,26.775 r0 top value=GRM1555C1H100JA01D
C44 "Comment" KEMET_T52X_D_7343-31_DensityB 36.435,45.775 r0 top value=T520D107M006ATE015
C45 "Comment" ?#1 13.685,19.275 r0 top value=GRM155R71E104KE14D
C46 "Comment" ?#1 41.685,18.275 r0 top value=GRM1555C1H330JA01D
C47 "Comment" ?#1 13.685,28.025 r0 top value=GRM1555C1H100JA01D
C48 "Comment" ?#1 22.685,39.525 r0 top value=GRM155R71E103KA01D
C49 "Comment" ?#1 35.185,56.025 r0 top value=GRM155R71E104KE14D
C50 "Comment" ?#1 18.685,58.525 r0 top value=GRM155R71E104KE14D
C51 "Comment" ?#1 61.685,58.525 r0 top value=GRM155R71E104KE14D
C52 "Comment" ?#1 20.435,58.525 r0 top value=GRM155R71E103KA01D
C53 "Comment" ?#1 63.435,58.525 r0 top value=GRM155R71E103KA01D
C54 "Comment" ?#1 22.185,58.525 r0 top value=GRM1555C1H330JA01D
C55 "Comment" ?#1 23.935,58.525 r180 top value=GRM1555C1H330JA01D
C56 "Comment" ?#1 25.685,58.525 r180 top value=GRM1555C1H330JA01D
C57 "Comment" ?#1 65.185,58.525 r0 top value=GRM1555C1H330JA01D
C58 "Comment" ?#1 66.935,58.525 r180 top value=GRM1555C1H330JA01D
C59 "Comment" ?#1 68.685,58.525 r0 top value=GRM1555C1H330JA01D
C60 "Comment" ?#1 63.435,12.275 r0 top value=GRM155R71E104KE14D
C61 "Comment" ?#2 65.685,12.275 r180 top value=GRM188R61A106KE69D
C62 "Comment" ?#1 61.685,9.525 r0 top value=GRM155R71E104KE14D
C63 "Comment" ?#1 50.935,17.025 r0 top value=GRM155R71C103KA01D
C64 "Comment" ?#1 61.985,23.425 r180 top value=GRM1555C1E470JA01D
C65 "Comment" ?#1 64.185,20.775 r0 top value=GRM155R71E104KE14D
C66 "Comment" ?#1 86.435,24.025 r0 top value=GRM155R71E104KE14D
C67 "Comment" ?#2 86.685,25.525 r0 top value=GRM188R61A106KE69D
C68 "Comment" ?#1 68.935,24.275 r180 top value=GRM155R71E104KE14D
C69 "Comment" ?#1 70.685,7.025 r0 top value=GRM1555C1H100JA01D
C70 "Comment" ?#1 70.685,8.275 r180 top value=GRM1555C1H100JA01D
C71 "Comment" ?#1 109.685,46.275 r0 top value=GRM155R71E104KE14D
C72 "Comment" ?#2 105.935,46.525 r0 top value=GRM188R61A106KE69D
C73 "Comment" ?#1 95.435,42.025 r180 top value=GRM155R71E104KE14D
C74 "Comment" ?#1 96.685,54.525 r0 top value=GRM155R71E104KE14D
C75 "Comment" ?#2 94.185,54.525 r0 top value=GRM188R61A106KE69D
C76 "Comment" ?#1 86.685,52.025 r180 top value=GRM155R71E103KA01D
C77 "Comment" ?#1 45.185,63.525 r0 top value=GRM155R72A472KA01D
C78 "Comment" ?#1 105.685,57.025 r0 top value=GRM155R71E103KA01D
C79 "Comment" ?#1 27.685,7.025 r180 top value=GRM1555C1H100JA01D
C80 "Comment" ?#1 25.935,7.025 r0 top value=GRM1555C1H100JA01D
D1 "Comment" Nexperia_PESD5V0S1UL_SOD882 13.935,32.775 r0 top value=PESD5V0S1UL
D2 "Comment" Nexperia_PESD5V0S1UL_SOD882 13.935,34.025 r0 top value=PESD5V0S1UL
D3 "Comment" PESD5V0C1BSF_SOD962-2 24.435,7.025 r0 top value=PESD5V0C1BSF
D4 "Comment" TI_DYA0002A_SOD523 61.935,5.025 r90 top value=TPD1E05U06DYAR
D5 "Comment" PESD5V0C1BSF_SOD962-2 69.185,7.025 r0 top value=PESD5V0C1BSF
D6 "Comment" TI_DYA0002A_SOD523 49.685,65.275 r90 top value=TPD1E05U06DYAR
D7 "Comment" TI_DYA0002A_SOD523 47.685,65.275 r90 top value=TPD1E05U06DYAR
D8 "Comment" TI_DYA0002A_SOD523 42.185,65.275 r90 top value=TPD1E05U06DYAR
D9 "Comment" TI_DYA0002A_SOD523 108.185,54.525 r0 top value=TPD1E05U06DYAR
D10 "Comment" TI_DYA0002A_SOD523 42.185,21.025 r0 top value=TPD1E05U06DYAR
D11 "Comment" TI_DYA0002A_SOD523 84.035,54.525 r0 top value=TPD1E05U06DYAR
FB1 "Comment" ?#4 42.685,23.025 r0 top value=BLM31KN601SN1L
FL1 "Comment" Abracon_ABSES5AF_1109-5 60.485,23.425 r270 top value=ABSES5AF-L100KM
H1 "Comment" ?#5 11.685,70.025 r0 top value=M3_NPTH
H2 "Comment" ?#5 108.685,70.025 r0 top value=M3_NPTH
H3 "Comment" ?#5 108.685,5.025 r0 top value=M3_NPTH
H4 "Comment" ?#5 8.685,5.025 r0 top value=M3_NPTH
J6 "Comment" TE_2336582-1_NanoSIM 24.685,66.525 r180 top value=2336582-1
J7 "Comment" TE_2336582-1_NanoSIM 67.685,66.525 r180 top value=2336582-1
J8 "Comment" Hirose_U.FL-R-SMT-1 19.685,3.525 r0 top value=U.FL-R-SMT-1(60)
J9 "Comment" Hirose_U.FL-R-SMT-1 57.185,7.025 r0 top value=U.FL-R-SMT-1(60)
J10 "Comment" Hirose_U.FL-R-SMT-1 77.685,3.525 r0 top value=U.FL-R-SMT-1(60)
J11 "Comment" USB_C_Receptacle_GCT_USB4105-xx-A_16P_TopMnt_Horizontal 45.685,71.35 r180 top value=USB4105-GF-A-120
J12 "Comment" GCT_MEM2052-00-195-00-A 90.685,64.9 r180 top value=MEM2052-00-195-00-A
J13 "Comment" Molex_504050-0291_PicoLock-2 109.89,60.025 r90 top value=504050-0291
J_MIC1 "Comment" Molex_Pico-Lock_504050-0691_1x06-1MP_P1.50mm_Horizontal 7.48,32.525 r270 top value=504050-0691
J_MIC2 "Comment" Molex_Pico-Lock_504050-0691_1x06-1MP_P1.50mm_Horizontal 43.685,3.82 r0 top value=504050-0691
J_MIC3 "Comment" Molex_Pico-Lock_504050-0691_1x06-1MP_P1.50mm_Horizontal 95.685,3.82 r0 top value=504050-0691
J_MIC4 "Comment" Molex_Pico-Lock_504050-0691_1x06-1MP_P1.50mm_Horizontal 109.89,21.025 r90 top value=504050-0691
J_PWR "Comment" Molex_43045-1202_MicroFit-12_RA 12.605,45.525 r90 top value=43045-1202
L1 "Comment" ?#6 57.435,34.275 r180 top value=LQH32PN2R2NN0L
L2 "Comment" ?#1 63.435,4.775 r90 top value=LQW15AN27NJ00D
Q1 "Comment" Nexperia_MMBT3904_SOT23 18.685,43.025 r0 top value=MMBT3904,215
Q2 "Comment" Nexperia_MMBT3904_SOT23 21.685,43.025 r0 top value=MMBT3904,215
Q3 "Comment" Nexperia_MMBT3904_SOT23 31.185,57.025 r0 top value=MMBT3904,215
Q4 "Comment" Vishay_Si1016X_SC-89 64.685,10.025 r0 top value=Si1016X-T1-GE3
R1 "Comment" ?#1 65.435,46.525 r0 top value=ERJ-2RKF1002X
R2 "Comment" ?#1 65.435,43.525 r0 top value=ERJ-2RKF1003X
R3 "Comment" ?#1 65.435,47.775 r0 top value=ERJ-2RKF1003X
R4 "Comment" ?#1 60.435,54.275 r0 top value=ERJ-2RKF1003X
R5 "Comment" ?#1 45.935,49.775 r0 top value=ERJ-2RKF1003X
R6 "Comment" ?#1 52.685,55.525 r0 top value=ERJ-2RKF1003X
R7 "Comment" ?#1 72.685,43.525 r0 top value=ERJ-2RKF1002X
R8 "Comment" ?#1 58.185,59.025 r0 top value=ERJ-2RKF22R0X
R9 "Comment" ?#1 64.185,55.275 r90 top value=ERJ-2RKF22R0X
R10 "Comment" ?#1 65.685,55.275 r90 top value=ERJ-2RKF22R0X
R11 "Comment" ?#1 67.185,55.275 r90 top value=ERJ-2RKF22R0X
R12 "Comment" ?#1 44.185,46.525 r0 top value=ERJ-2RKF22R0X
R13 "Comment" ?#1 67.185,46.525 r0 top value=ERJ-2RKF2201X
R14 "Comment" ?#1 44.185,43.525 r0 top value=ERJ-2RKF2201X
R15 "Comment" ?#1 67.185,43.525 r0 top value=ERJ-2RKF22R0X
R16 "Comment" ?#1 45.935,38.525 r180 top value=ERJ-2RKF22R0X
R17 "Comment" ?#1 63.435,34.775 r0 top value=ERJ-2RKF22R0X
R18 "Comment" ?#1 68.685,31.025 r0 top value=ERJ-2RKF22R0X
R19 "Comment" ?#1 12.185,32.525 r0 top value=ERJ-2RKF1003X
R20 "Comment" ?#1 41.935,9.525 r0 top value=ERJ-2RKF1003X
R21 "Comment" ?#1 93.185,9.775 r0 top value=ERJ-2RKF1003X
R22 "Comment" ?#1 103.685,23.275 r0 top value=ERJ-2RKF1003X
R23 "Comment" ?#1 57.185,27.275 r180 top value=ERJ-2RKF1003X
R24 "Comment" ?#1 15.685,40.775 r0 top value=ERJ-2RKF4701X
R25 "Comment" ?#1 18.185,45.525 r0 top value=ERJ-2RKF4702X
R26 "Comment" ?#1 17.435,40.775 r0 top value=ERJ-2RKF4701X
R27 "Comment" ?#1 19.185,40.775 r0 top value=ERJ-2RKF4702X
R28 "Comment" ?#1 20.935,39.525 r0 top value=ERJ-2RKF1002X
R29 "Comment" ?#1 20.935,45.525 r0 top value=ERJ-2RKF1003X
R30 "Comment" ?#1 17.435,39.525 r0 top value=ERJ-2RKF1002X
R31 "Comment" ?#1 15.685,39.525 r0 top value=ERJ-2RKF1002X
R32 "Comment" ?#1 20.935,46.775 r0 top value=ERJ-2RKF1003X
R33 "Comment" ?#1 20.935,40.775 r0 top value=ERJ-2RKF1003X
R34 "Comment" ?#1 19.185,39.525 r0 top value=ERJ-2RKF1003X
R35 "Comment" ?#1 41.685,17.025 r0 top value=ERJ-2RKF1003X
R36 "Comment" ?#1 13.685,29.275 r0 top value=ERJ-2RKF22R0X
R37 "Comment" ?#1 43.435,19.525 r0 top value=ERJ-2RKF22R0X
R38 "Comment" ?#1 41.685,15.775 r0 top value=ERJ-2RKF1001X
R39 "Comment" ?#1 13.685,24.275 r180 top value=ERJ-2GE0R00X
R40 "Comment" ?#1 13.685,23.025 r180 top value=ERJ-2GE0R00X
R41 "Comment" ?#1 43.435,18.275 r0 top value=ERJ-2RKF1001X
R42 "Comment" ?#1 13.685,18.025 r0 top value=ERJ-2GE0R00X
R43 "Comment" ?#1 29.435,7.025 r180 top value=ERJ-2GE0R00X
R44 "Comment" ?#1 35.185,57.275 r180 top value=ERJ-2RKF4702X
R45 "Comment" ?#1 40.185,62.025 r180 top value=ERJ-2RKF1003X
R46 "Comment" ?#1 31.185,59.275 r0 top value=ERJ-2RKF1002X
R47 "Comment" ?#1 35.185,58.525 r0 top value=ERJ-2RKF1003X
R48 "Comment" ?#1 18.685,57.275 r180 top value=ERJ-2RKF1002X
R49 "Comment" ?#1 61.685,57.275 r0 top value=ERJ-2RKF1002X
R50 "Comment" ?#1 27.435,58.525 r0 top value=ERJ-2GE0R00X
R51 "Comment" ?#1 28.685,54.275 r0 top value=ERJ-2GE0R00X
R52 "Comment" ?#1 28.435,57.275 r180 top value=ERJ-2GE0R00X
R53 "Comment" ?#1 70.435,58.525 r0 top value=ERJ-2GE0R00X
R54 "Comment" ?#1 72.185,58.525 r0 top value=ERJ-2GE0R00X
R55 "Comment" ?#1 70.435,57.275 r180 top value=ERJ-2GE0R00X
R56 "Comment" ?#1 50.935,18.275 r180 top value=ERJ-2RKF22R0X
R57 "Comment" ?#1 67.435,45.025 r0 top value=ERJ-2RKF22R0X
R58 "Comment" ?#1 50.935,15.775 r180 top value=ERJ-2RKF22R0X
R59 "Comment" ?#1 64.685,15.275 r0 top value=ERJ-2GEJ561X
R60 "Comment" ?#1 52.185,10.025 r0 top value=ERJ-2GEJ104X
R61 "Comment" ?#1 52.685,23.525 r90 top value=ERJ-2GEJ104X
R62 "Comment" ?#4 57.185,23.775 r0 top value=ERJ-8GEYJ100V
R63 "Comment" ?#1 68.935,20.025 r180 top value=ERJ-2RKF1003X
R64 "Comment" ?#1 86.435,20.025 r0 top value=ERJ-2RKF1003X
R65 "Comment" ?#1 68.935,21.275 r0 top value=ERJ-2RKF1003X
R66 "Comment" ?#1 86.435,21.275 r0 top value=ERJ-2RKF1003X
R67 "Comment" ?#1 68.935,18.775 r180 top value=ERJ-2RKF1002X
R68 "Comment" ?#1 86.435,18.775 r180 top value=ERJ-2RKF1002X
R69 "Comment" ?#1 44.185,47.775 r180 top value=ERJ-2RKF22R0X
R70 "Comment" ?#1 67.185,47.775 r0 top value=ERJ-2RKF22R0X
R71 "Comment" ?#1 44.185,42.275 r180 top value=ERJ-2RKF22R0X
R72 "Comment" ?#1 68.935,22.525 r180 top value=ERJ-2RKF22R0X
R73 "Comment" ?#1 70.685,5.775 r0 top value=ERJ-2GE0R00X
R74 "Comment" ?#1 105.935,33.275 r0 top value=ERJ-2RKF22R0X
R75 "Comment" ?#1 67.185,42.275 r0 top value=ERJ-2RKF22R0X
R76 "Comment" ?#1 89.185,42.525 r0 top value=ERJ-2RKF1002X
R77 "Comment" ?#1 89.185,41.275 r0 top value=ERJ-2RKF1003X
R78 "Comment" ?#1 96.685,37.025 r180 top value=ERJ-2RKF1002X
R79 "Comment" ?#1 47.935,54.275 r180 top value=ERJ-2RKF22R0X
R80 "Comment" ?#1 86.685,50.775 r0 top value=ERJ-2RKF22R0X
R81 "Comment" ?#1 91.935,52.025 r0 top value=ERJ-2RKF22R0X
R82 "Comment" ?#1 88.435,50.775 r0 top value=ERJ-2RKF22R0X
R83 "Comment" ?#1 93.685,52.025 r0 top value=ERJ-2RKF22R0X
R84 "Comment" ?#1 95.435,52.025 r0 top value=ERJ-2RKF22R0X
R85 "Comment" ?#1 97.185,52.025 r0 top value=ERJ-2RKF1002X
R86 "Comment" ?#1 88.435,52.025 r0 top value=ERJ-2RKF1002X
R87 "Comment" ?#1 90.185,50.775 r0 top value=ERJ-2RKF1002X
R88 "Comment" ?#1 93.685,50.775 r0 top value=ERJ-2RKF1002X
R89 "Comment" ?#1 90.185,52.025 r0 top value=ERJ-2RKF1002X
R90 "Comment" ?#1 84.685,52.025 r0 top value=ERJ-2RKF1002X
R91 "Comment" ?#1 67.685,49.775 r0 top value=ERJ-2RKF22R0X
R92 "Comment" ?#1 67.685,48.775 r0 top value=ERJ-2RKF22R0X
R93 "Comment" ?#1 47.685,63.525 r0 top value=ERJ-2RKF5101X
R94 "Comment" ?#1 42.185,63.525 r0 top value=ERJ-2RKF5101X
R95 "Comment" ?#1 50.685,60.025 r0 top value=ERJ-2RKF1001X
R96 "Comment" ?#1 45.935,52.275 r0 top value=ERJ-2RKF1003X
R97 "Comment" ?#1 46.685,62.275 r0 top value=ERJ-2RKF1004X
R98 "Comment" ?#1 43.685,62.275 r0 top value=ERJ-2GE0R00X
R99 "Comment" ?#1 105.685,58.275 r0 top value=ERJ-2RKF1002X
R100 "Comment" ?#1 99.685,47.025 r180 top value=ERJ-2RKF1001X
R101 "Comment" ?#1 42.185,44.025 r0 top value=ERJ-2RKF22R0X
R102 "Comment" ?#1 42.185,42.025 r180 top value=ERJ-2RKF1001X
R103 "Comment" ?#1 30.685,52.525 r0 top value=ERJ-2GE0R00X
TP_BLE_SWD "Comment" ?#7 87.685,52.025 r180 bottom value=TEST_PADS
TP_CELL_DBG "Comment" ?#8 50.685,45.025 r180 bottom value=TEST_PADS
TP_CELL_USB "Comment" ?#7 36.685,45.025 r180 bottom value=TEST_PADS
TP_EOL "Comment" ?#9 36.685,52.025 r180 bottom value=TEST_PADS
TP_MCU_SWD "Comment" ?#8 72.685,52.025 r180 bottom value=TEST_PADS
U1 "Comment" ST_STM32U585_LQFP100_1L 55.685,45.025 r0 top value=STM32U585VIT6Q
U2 "Comment" Winbond_W25Q512JV_PackageF_IPC_Candidate 79.685,43.525 r0 top value=W25Q512JVFIQ
U3 "Comment" ST_LIS2DW12_LGA-12L 69.685,44.525 r0 top value=LIS2DW12TR
U4 "Comment" STTS22H_UDFN-6L 69.685,38.525 r0 top value=STTS22HTR
U5 "Comment" LT6000_DCB-7 64.685,18.025 r0 top value=LT6000IDCB#TRMPBF
U6 "Comment" TI_DBV0005A_SOT23-5 94.185,39.525 r0 top value=SN74LVC1G07DBVR
U7 "Comment" TI_PW0024A_TSSOP24 63.435,29.775 r0 top value=SN74AXC8T245PWR
U8 "Comment" Quectel_BG95-M3_LGA-102 27.685,23.025 r0 top value=BG95-M3
U9 "Comment" u-blox_MAX-M10S_LCC-18 57.185,17.025 r0 top value=MAX-M10S-00B
U10 "Comment" Ebyte_E22-M22S_Castellated-22 77.685,20.025 r0 top value=E22-900M22S
U11 "Comment" Raytac_MDBT50Q-P1MV2 105.935,39.775 r270 top value=MDBT50Q-P1MV2
U13 "Comment" TI_PW0024A_TSSOP24 40.185,57.025 r0 top value=TS3A27518EPWR
U14 "Comment" ST_ESDALC6V1-5P6_SOT666 25.685,55.525 r0 top value=ESDALC6V1-5P6
U15 "Comment" ST_ESDALC6V1-5P6_SOT666 77.185,63.025 r0 top value=ESDALC6V1-5P6
U16 "Comment" TI_PW0024A_TSSOP24 27.685,42.275 r0 top value=SN74AXC8T245PWR
U17 "Comment" TI_PW0014A_TSSOP14 50.685,29.025 r0 top value=SN74LVC32APWR
U18 "Comment" TI_DRL0006A_SOT6 57.185,29.025 r0 top value=SN74AXC1T45DRLR
U19 "Comment" TI_DQA0010A_USON10 12.435,36.525 r0 top value=TPD4E05U06DQAR
U20 "Comment" TI_DQA0010A_USON10 41.935,13.025 r0 top value=TPD4E05U06DQAR
U21 "Comment" TI_DQA0010A_USON10 95.685,9.775 r0 top value=TPD4E05U06DQAR
U22 "Comment" TI_DQA0010A_USON10 104.435,21.025 r0 top value=TPD4E05U06DQAR
U23 "Comment" TI_DQA0010A_USON10 86.685,54.025 r0 top value=TPD4E05U06DQAR
U24 "Comment" TI_DQA0010A_USON10 91.685,54.025 r0 top value=TPD4E05U06DQAR
U25 "Comment" TI_DRT0003A_IPC_Candidate 45.685,65.775 r180 top value=TPD2EUSB30DRTR
U26 "Comment" TI_DRT0003A_IPC_Candidate 12.185,23.525 r270 top value=TPD2EUSB30DRTR
U27 "Comment" TI_DQA0010A_USON10 44.685,10.025 r0 top value=TPD4E05U06DQAR
X1 "Comment" SiT1552_JE_CSP-4 65.435,45.025 r0 top value=SiT1552AI-JE-DCC-32.768D

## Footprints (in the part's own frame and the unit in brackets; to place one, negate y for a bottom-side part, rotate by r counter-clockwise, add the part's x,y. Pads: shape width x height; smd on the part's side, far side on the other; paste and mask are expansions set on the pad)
Abracon_ABSES5AF_1109-5 [mm]
  rect 0.25x0.3 smd mask+0: A(0.375,-0.25) B(0,-0.25) C(-0.375,0) D(0,0.25) E(0.375,0.25)
Ebyte_E22-M22S_Castellated-22 [mm]
  rect 0.9x0.8 smd mask+0: 1(7.45,-9) 2(7.45,-7.73) 3(7.45,-6.46) 4(7.45,-0.89) 5(7.45,0.38) 6(7.45,1.65) 7(7.45,2.92) 8(7.45,4.19) 9(7.45,5.46) 10(7.45,6.73) 11(7.45,8) 12(-7.45,8) 13(-7.45,6.73) 14(-7.45,5.46) 15(-7.45,4.19) 16(-7.45,2.92) 17(-7.45,1.65) 18(-7.45,0.38) 19(-7.45,-0.89) 20(-7.45,-6.46) 21(-7.45,-7.73) 22(-7.45,-9)
  silkscreen extent 7.15,-9.45 7.15,-8.55
GCT_MEM2052-00-195-00-A [mm]
  rect 0.8x1.5 smd mask+0: 1(1.905,-3.635)
  rrect20% 0.8x1.5 smd mask+0: 2(0.805,-3.235) 3(-0.295,-3.635) 4(-1.395,-3.835) 5(-2.495,-3.635) 6(-3.595,-3.835) 7(-4.695,-3.635) 8(-5.795,-3.635)
  rect 1x1.04 smd mask+0: CD(-3.585,7.595)
  rect 1.4x1.9 smd mask+0: SHIELD(-6.575,-5.925) SHIELD(6.575,-6.925)
  rect 1.2x1.4 smd mask+0: SHIELD(-5.035,7.225)
  rect 1.3x1.4 smd mask+0: SHIELD(0.715,7.225)
Hirose_U.FL-R-SMT-1 [mm]
  rect 1.05x1 smd paste-1.05 mask+0: 1(-1.05,0)
  rect 2.2x1.05 smd paste-2.2 mask+0: SHIELD(0.475,-1.475) SHIELD(0.475,1.475)
  rect 0.85x0.8 on Top Paste mask-0.85: Un1(-1.05,0)
  rect 2x0.9 on Top Paste mask-2: Un2(0.475,1.475) Un3(0.475,-1.475)
KEMET_T52X_D_7343-31_DensityB [mm]
  rect 2.37x2.43 smd mask+0: 1(-3.12,0) 2(3.12,0)
  silkscreen extent -4.42,-1.35 -3.92,1.35
LT6000_DCB-7 [mm]
  rect 0.25x0.7 smd mask+0: 1(0.5,-1.425)
  rrect20% 0.25x0.7 smd mask+0: 2(0,-1.425) 3(-0.5,-1.425) 4(-0.5,1.425) 5(0,1.425) 6(0.5,1.425)
  rect 1.35x1.65 smd mask+0: EP(0,0)
  silkscreen extent 0.65,-1.62 1.05,-1.62
Molex_43045-1202_MicroFit-12_RA [mm]
  rrect20% 1.5x1.5 hole 1.02 paste-2539.97 mask+0: 1(0,0)
  round 1.5 hole 1.02 paste-2539.97 mask+0: 2(3,0) 3(6,0) 4(9,0) 5(12,0) 6(15,0) 7(0,-3) 8(3,-3) 9(6,-3) 10(9,-3) 11(12,-3) 12(15,-3)
  round 3 hole 3 paste-2539.97 mask+0: Un1(2.15,4.32) Un2(12.85,4.32)
Molex_504050-0291_PicoLock-2 [mm]
  rect 0.6x1 smd mask+0: 1(-0.75,2.795)
  rrect20% 0.6x1 smd mask+0: 2(0.75,2.795)
  rect 1.25x1.8 smd mask+0: Un1(-3.355,-2.395) Un2(3.355,-2.395)
Molex_Pico-Lock_504050-0691_1x06-1MP_P1.50mm_Horizontal [mm]
  rrect25% 0.6x1 smd mask+0: 1(-3.75,2.795) 2(-2.25,2.795) 3(-0.75,2.795) 4(0.75,2.795) 5(2.25,2.795) 6(3.75,2.795)
  rrect20% 1.25x1.8 smd mask+0: Un1(-6.355,-2.395) Un2(6.355,-2.395)
  silkscreen extent -6.49,-3.42 6.49,3.29
Nexperia_MMBT3904_SOT23 [mm]
  rect 0.7x0.6 smd paste-0.7 mask+0.075: 1(-1,0.95) 2(-1,-0.95) 3(1,0)
  rect 0.6x0.5 on Top Paste mask-0.6: Un1(-1,0.95) Un2(-1,-0.95) Un3(1,0)
  silkscreen extent -1.35,1.43 -0.95,1.63
Nexperia_PESD5V0S1UL_SOD882 [mm]
  rrect25% 0.4x0.7 smd paste-0.7 mask+0.05: 1(-0.35,0) 2(0.35,0)
  rrect33% 0.3x0.6 on Top Paste mask-0.6: Un1(-0.35,0) Un2(0.35,0)
  silkscreen extent -0.72,0.32 -0.44,0.46
PESD5V0C1BSF_SOD962-2 [mm]
  rect 0.256x0.2 smd mask+0: 1(-0.2,0)
  rrect25% 0.256x0.2 smd mask+0: 2(0.2,0)
  silkscreen extent -0.48,-0.32 -0.48,0.32
Quectel_BG95-M3_LGA-102 [mm]
  rect 1.1x0.7 smd mask+0: 1(-9.15,9.7)
  rrect20% 1.1x0.7 smd mask+0: 2(-9.15,8.6) 3(-9.15,7.5) 4(-9.15,6.4) 5(-9.15,5.3) 6(-9.15,4.2) 7(-9.15,3.1) 8(-9.15,2) 9(-9.15,0.9) 10(-9.15,-0.2) 11(-9.15,-1.9) 12(-9.15,-3) 13(-9.15,-4.1) 14(-9.15,-5.2) 15(-9.15,-6.3) 16(-9.15,-7.4) 17(-9.15,-8.5) 18(-9.15,-9.6) 32(9.15,-9.6) 33(9.15,-8.5) 34(9.15,-7.4) 35(9.15,-6.3) 36(9.15,-5.2) 37(9.15,-4.1) 38(9.15,-3) 39(9.15,-1.9) 40(9.15,-0.2) 41(9.15,0.9) 42(9.15,2) 43(9.15,3.1) 44(9.15,4.2) 45(9.15,5.3) 46(9.15,6.4) 47(9.15,7.5) 48(9.15,8.6) 49(9.15,9.7)
  rrect20% 0.7x1.1 smd mask+0: 19(-7.45,-11) 20(-6.35,-11) 21(-5.25,-11) 22(-4.15,-11) 23(-3.05,-11) 24(-1.95,-11) 25(0.55,-11) 26(1.65,-11) 27(2.75,-11) 28(3.85,-11) 29(4.95,-11) 30(6.05,-11) 31(7.15,-11) 50(7.15,11) 51(6.05,11) 52(4.95,11) 53(3.85,11) 54(2.75,11) 55(1.65,11) 56(0.55,11) 57(-1.95,11) 58(-3.05,11) 59(-4.15,11) 60(-5.25,11) 61(-6.35,11) 62(-7.45,11)
  rrect20% 1x1 smd mask+0: 63(-5.95,4.25) 64(-5.95,2.55) 65(-5.95,0.85) 66(-5.95,-0.85) 67(-5.95,-2.55) 68(-5.95,-4.25) 69(-2.55,-7.65) 70(-0.85,-7.65) 71(0.85,-7.65) 72(2.55,-7.65) 73(5.95,-4.25) 74(5.95,-2.55) 75(5.95,-0.85) 76(5.95,0.85) 77(5.95,2.55) 78(5.95,4.25) 79(2.55,7.65) 80(0.85,7.65) 81(-0.85,7.65) 82(-2.55,7.65) 83(-4.25,4.25) 84(-4.25,2.55) 85(-4.25,0.85) 86(-4.25,-0.85) 87(-4.25,-2.55) 88(-4.25,-4.25) 89(-2.55,-5.95) 90(-0.85,-5.95) 91(0.85,-5.95) 92(2.55,-5.95) 93(4.25,-4.25) 94(4.25,-2.55) 95(4.25,-0.85) 96(4.25,0.85) 97(4.25,2.55) 98(4.25,4.25) 99(2.55,5.95) 100(0.85,5.95) 101(-0.85,5.95) 102(-2.55,5.95)
  silkscreen extent -10.1,-11.95 10.1,11.95
Raytac_MDBT50Q-P1MV2 [mm]
  rect 0.6x0.4 smd mask+0: 1(-4.65,3.75) 2(-4.65,2.65) 3(-4.65,1.85) 4(-4.65,0.25) 5(-3.75,-0.15) 6(-4.65,-0.55) 7(-3.75,-0.95) 8(-4.65,-1.35) 9(-3.75,-1.75) 10(-4.65,-2.15) 11(-3.75,-2.55) 12(-4.65,-2.95) 13(-3.75,-3.35) 14(-4.65,-3.75) 34(4.65,-6.15) 35(4.65,-5.35) 36(3.75,-4.95) 37(4.65,-4.55) 38(3.75,-4.15) 39(4.65,-3.75) 40(3.75,-3.35) 41(4.65,-2.95) 42(3.75,-2.55) 43(3.75,-1.75) 44(4.65,-1.35) 45(3.75,-0.95) 46(4.65,-0.55) 47(3.75,-0.15) 48(4.65,0.25) 49(3.75,0.65) 50(3.75,1.45) 51(4.65,1.85) 52(3.75,2.25) 53(4.65,2.65) 54(3.75,3.05) 55(4.65,3.75)
  rect 0.4x0.6 smd mask+0: 15(-4.8,-7.15) 16(-4,-7.15) 17(-3.2,-7.15) 18(-2.4,-7.15) 19(-2,-6.25) 20(-1.6,-7.15) 21(-1.2,-6.25) 22(-0.8,-7.15) 23(-0.4,-6.25) 24(0,-7.15) 25(0.4,-6.25) 26(0.8,-7.15) 27(1.2,-6.25) 28(1.6,-7.15) 29(2,-6.25) 30(2.4,-7.15) 31(3.2,-7.15) 32(4,-7.15) 33(4.8,-7.15) 56(-2,-0.55) 57(-1.2,-0.55) 58(-0.4,-0.55) 59(0.4,-0.55) 60(1.2,-0.55) 61(2,-0.55)
SiT1552_JE_CSP-4 [mm]
  round 0.25 smd mask+0.05: 1(-0.5,-0.205) 2(0.5,-0.205) 3(0.5,0.205) 4(-0.5,0.205)
  silkscreen extent -0.77,-0.54 -0.37,-0.54
ST_ESDALC6V1-5P6_SOT666 [mm]
  rect 0.99x0.3 smd mask+0: 1(-0.805,0.5) 2(-0.805,0) 3(-0.805,-0.5) 4(0.805,-0.5) 5(0.805,0) 6(0.805,0.5)
  silkscreen extent -1.48,0.57 -1.08,0.77
ST_LIS2DW12_LGA-12L [mm]
  rect 0.375x0.35 smd mask+0.05: 1(-0.763,0.75) 2(-0.763,0.25) 3(-0.763,-0.25) 4(-0.763,-0.75) 7(0.763,-0.75) 8(0.763,-0.25) 9(0.763,0.25) 10(0.763,0.75)
  rect 0.35x0.375 smd mask+0.05: 5(-0.25,-0.763) 6(0.25,-0.763) 11(0.25,0.763) 12(-0.25,0.763)
ST_STM32U585_LQFP100_1L [mm]
  rect 1.2x0.3 smd mask+0: 1(-7.75,6) 2(-7.75,5.5) 3(-7.75,5) 4(-7.75,4.5) 5(-7.75,4) 6(-7.75,3.5) 7(-7.75,3) 8(-7.75,2.5) 9(-7.75,2) 10(-7.75,1.5) 11(-7.75,1) 12(-7.75,0.5) 13(-7.75,0) 14(-7.75,-0.5) 15(-7.75,-1) 16(-7.75,-1.5) 17(-7.75,-2) 18(-7.75,-2.5) 19(-7.75,-3) 20(-7.75,-3.5) 21(-7.75,-4) 22(-7.75,-4.5) 23(-7.75,-5) 24(-7.75,-5.5) 25(-7.75,-6) 51(7.75,-6) 52(7.75,-5.5) 53(7.75,-5) 54(7.75,-4.5) 55(7.75,-4) 56(7.75,-3.5) 57(7.75,-3) 58(7.75,-2.5) 59(7.75,-2) 60(7.75,-1.5) 61(7.75,-1) 62(7.75,-0.5) 63(7.75,0) 64(7.75,0.5) 65(7.75,1) 66(7.75,1.5) 67(7.75,2) 68(7.75,2.5) 69(7.75,3) 70(7.75,3.5) 71(7.75,4) 72(7.75,4.5) 73(7.75,5) 74(7.75,5.5) 75(7.75,6)
  rect 0.3x1.2 smd mask+0: 26(-6,-7.75) 27(-5.5,-7.75) 28(-5,-7.75) 29(-4.5,-7.75) 30(-4,-7.75) 31(-3.5,-7.75) 32(-3,-7.75) 33(-2.5,-7.75) 34(-2,-7.75) 35(-1.5,-7.75) 36(-1,-7.75) 37(-0.5,-7.75) 38(0,-7.75) 39(0.5,-7.75) 40(1,-7.75) 41(1.5,-7.75) 42(2,-7.75) 43(2.5,-7.75) 44(3,-7.75) 45(3.5,-7.75) 46(4,-7.75) 47(4.5,-7.75) 48(5,-7.75) 49(5.5,-7.75) 50(6,-7.75) 76(6,7.75) 77(5.5,7.75) 78(5,7.75) 79(4.5,7.75) 80(4,7.75) 81(3.5,7.75) 82(3,7.75) 83(2.5,7.75) 84(2,7.75) 85(1.5,7.75) 86(1,7.75) 87(0.5,7.75) 88(0,7.75) 89(-0.5,7.75) 90(-1,7.75) 91(-1.5,7.75) 92(-2,7.75) 93(-2.5,7.75) 94(-3,7.75) 95(-3.5,7.75) 96(-4,7.75) 97(-4.5,7.75) 98(-5,7.75) 99(-5.5,7.75) 100(-6,7.75)
  silkscreen extent -8.08,6.41 -7.4,6.88
STTS22H_UDFN-6L [mm]
  rect 0.27x0.7 smd mask+0: 1(-0.65,-0.865)
  rrect20% 0.27x0.7 smd mask+0: 2(0,-0.865) 3(0.65,-0.865) 4(0.65,0.865) 5(0,0.865) 6(-0.65,0.865)
  rect 1.45x0.65 smd mask+0: EP(0,0)
  silkscreen extent -0.98,-0.98 -0.82,-0.82
TE_2336582-1_NanoSIM [mm]
  rect 0.8x1.14 smd mask+0: 1(1.905,5.43) 2(-0.635,5.43) 3(-3.175,5.43) 4(3.175,5.43) 5(0.635,5.43) 6(-1.905,5.43)
  rect 0.89x2.05 smd mask+0: 7(4.125,4.405)
  rect 1.5x2.1 smd mask+0: SHIELD(-6.5,-3.95) SHIELD(6.5,-3.95)
  round 1.2 hole 1.2 paste-2539.97 mask+0: Un1(-2.54,2.5) Un2(-2.54,-3.94) Un3(0,2.5) Un4(0,-3.94) Un5(2.54,2.5) Un6(2.54,-3.94)
TI_DBV0005A_SOT23-5 [mm]
  rrect17% 1.1x0.6 smd mask+0.07: 1(-1.3,0.95) 2(-1.3,0) 3(-1.3,-0.95) 4(1.3,-0.95) 5(1.3,0.95)
  silkscreen extent -1.68,1.08 -1.28,1.28
TI_DQA0010A_USON10 [mm]
  rrect50% 0.565x0.2 smd mask+0.07: 1(-0.417,1) 2(-0.417,0.5) 4(-0.417,-0.5) 5(-0.417,-1) 6(0.417,-1) 7(0.417,-0.5) 9(0.417,0.5) 10(0.417,1)
  rrect25% 0.565x0.4 smd paste-0.565 mask+0.07: 3(-0.417,0) 8(0.417,0)
  rrect28% 0.565x0.36 on Top Paste mask-0.565: Un1(-0.417,0) Un2(0.417,0)
  silkscreen extent -0.88,1.1 -0.48,1.35
TI_DRL0006A_SOT6 [mm]
  rrect33% 0.67x0.3 smd mask+0.05: 1(-0.74,0.5) 2(-0.74,0) 3(-0.74,-0.5) 4(0.74,-0.5) 5(0.74,0) 6(0.74,0.5)
  silkscreen extent -1.2,0.67 -0.8,0.92
TI_DRT0003A_IPC_Candidate [mm]
  rrect25% 0.3x0.3 smd mask+0: 1(-0.35,-0.425) 2(0.35,-0.425) 3(0,0.425)
  silkscreen extent -1.04,-0.71 -0.76,-0.43
TI_DYA0002A_SOD523 [mm]
  rrect25% 0.67x0.4 smd mask+0.05: 1(-0.74,0) 2(0.74,0)
  silkscreen extent -1.18,0.46 -0.82,0.64
TI_PW0014A_TSSOP14 [mm]
  rrect11% 1.5x0.45 smd mask+0.05: 1(-2.9,1.95) 2(-2.9,1.3) 3(-2.9,0.65) 4(-2.9,0) 5(-2.9,-0.65) 6(-2.9,-1.3) 7(-2.9,-1.95) 8(2.9,-1.95) 9(2.9,-1.3) 10(2.9,-0.65) 11(2.9,0) 12(2.9,0.65) 13(2.9,1.3) 14(2.9,1.95)
  silkscreen extent -3.16,2.1 -2.52,2.55
TI_PW0024A_TSSOP24 [mm]
  rrect11% 1.5x0.45 smd mask+0.05: 1(-2.9,3.575) 2(-2.9,2.925) 3(-2.9,2.275) 4(-2.9,1.625) 5(-2.9,0.975) 6(-2.9,0.325) 7(-2.9,-0.325) 8(-2.9,-0.975) 9(-2.9,-1.625) 10(-2.9,-2.275) 11(-2.9,-2.925) 12(-2.9,-3.575) 13(2.9,-3.575) 14(2.9,-2.925) 15(2.9,-2.275) 16(2.9,-1.625) 17(2.9,-0.975) 18(2.9,-0.325) 19(2.9,0.325) 20(2.9,0.975) 21(2.9,1.625) 22(2.9,2.275) 23(2.9,2.925) 24(2.9,3.575)
  silkscreen extent -3.16,3.73 -2.52,4.08
u-blox_MAX-M10S_LCC-18 [mm]
  rect 0.7x1.8 smd paste-1.8 mask+0: 1(-4.4,-4.75) 9(4.4,-4.75) 10(4.4,4.75) 18(-4.4,4.75)
  rect 0.8x1.8 smd paste-1.8 mask+0: 2(-3.3,-4.75) 3(-2.2,-4.75) 4(-1.1,-4.75) 5(0,-4.75) 6(1.1,-4.75) 7(2.2,-4.75) 8(3.3,-4.75) 11(3.3,4.75) 12(2.2,4.75) 13(1.1,4.75) 14(0,4.75) 15(-1.1,4.75) 16(-2.2,4.75) 17(-3.3,4.75)
  silkscreen extent -5.05,-5 -4.55,-5
USB_C_Receptacle_GCT_USB4105-xx-A_16P_TopMnt_Horizontal [mm]
  rrect25% 0.6x1.11 smd mask+0: A1(-3.2,3.68) A12(3.2,3.68) B1(3.2,3.68) B12(-3.2,3.68)
  rrect25% 0.6x1.15 smd mask+0: A4(-2.4,3.68) A9(2.4,3.68) B4(2.4,3.68) B9(-2.4,3.68)
  rrect25% 0.3x1.15 smd mask+0: A5(-1.25,3.68) A6(-0.25,3.68) A7(0.25,3.68) A8(1.25,3.68) B5(1.75,3.68) B6(0.75,3.68) B7(-0.75,3.68) B8(-1.75,3.68)
  rrect100% 1x2.1 hole 1.7 slot 0.6 at 0 deg mask+0: SHIELD(-4.32,3.105) SHIELD(4.32,3.105)
  rrect100% 1x1.8 hole 1.4 slot 0.6 at 0 deg mask+0: SHIELD(-4.32,-1.075) SHIELD(4.32,-1.075)
  round 0.65 hole 0.65 paste-2539.97 mask+0: Un1(-2.89,2.605) Un2(2.89,2.605)
  silkscreen extent -4.67,0.1 4.67,1.8
Vishay_Si1016X_SC-89 [mm]
  rect 0.478x0.3 smd mask+0: 1(-0.638,0.5) 2(-0.638,0) 3(-0.638,-0.5) 4(0.638,-0.5) 5(0.638,0) 6(0.638,0.5)
  silkscreen extent -1.08,0.57 -0.68,0.77
Winbond_W25Q512JV_PackageF_IPC_Candidate [mm]
  rrect25% 2.05x0.6 smd mask+0: 1(-4.65,4.445) 2(-4.65,3.175) 3(-4.65,1.905) 4(-4.65,0.635) 5(-4.65,-0.635) 6(-4.65,-1.905) 7(-4.65,-3.175) 8(-4.65,-4.445) 9(4.65,-4.445) 10(4.65,-3.175) 11(4.65,-1.905) 12(4.65,-0.635) 13(4.65,0.635) 14(4.65,1.905) 15(4.65,3.175) 16(4.65,4.445)
  silkscreen extent -5.05,5 -4.37,5.48
?#1 [mm]
  rrect20% 0.45x0.5 smd mask+0: 1(-0.325,0) 2(0.325,0)
?#2 [mm]
  rrect20% 0.7x0.8 smd mask+0: 1(-0.45,0) 2(0.45,0)
?#3 [mm]
  rrect20% 1x1.2 smd mask+0: 1(-0.6,0) 2(0.6,0)
?#4 [mm]
  rrect20% 1.4x1.6 smd mask+0: 1(-0.9,0) 2(0.9,0)
?#5 [mm]
  round 3.2 hole 3.2 paste-2539.97 mask-3.2: Un1(0,0)
?#6 [mm]
  rrect20% 1.4x2.4 smd mask+0: 1(-0.9,0) 2(0.9,0)
?#7 [mm]
  round 1.7 smd paste-1.7 mask+0.2: 1(0,0) 2(-2.54,0) 3(-5.08,0) 4(-7.62,0)
?#8 [mm]
  round 1.7 smd paste-1.7 mask+0.2: 1(0,0) 2(-2.54,0) 3(-5.08,0) 4(-7.62,0) 5(-10.16,0)
?#9 [mm]
  round 1.7 smd paste-1.7 mask+0.2: 1(0,0) 2(-2.54,0) 3(-5.08,0) 4(-7.62,0) 5(-10.16,0) 6(-12.7,0) 7(-15.24,0) 8(-17.78,0) 9(-20.32,0) 10(-22.86,0) 11(-25.4,0) 12(-27.94,0) 13(-30.48,0)

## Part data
C1 C2 C3 C4 C5 C7 C8 C9 C10 C11 C12 C14 C15 C16 C17 C18 C21 C22 C23 C25 C26 C27 C28 C29 C30 C31 C32 C33 C34 C35 C37 C38 C39 C40 C41 C42 C43 C45 C46 C47 C48 C49 C50 C51 C52 C53 C54 C55 C56 C57 C58 C59 C60 C62 C63 C64 C65 C66 C68 C69 C70 C71 C73 C74 C76 C77 C78 C79 C80 L2 R1 R2 R3 R4 R5 R6 R7 R8 R9 R10 R11 R12 R13 R14 R15 R16 R17 R18 R19 R20 R21 R22 R23 R24 R25 R26 R27 R28 R29 R30 R31 R32 R33 R34 R35 R36 R37 R38 R39 R40 R41 R42 R43 R44 R45 R46 R47 R48 R49 R50 R51 R52 R53 R54 R55 R56 R57 R58 R59 R60 R61 R63 R64 R65 R66 R67 R68 R69 R70 R71 R72 R73 R74 R75 R76 R77 R78 R79 R80 R81 R82 R83 R84 R85 R86 R87 R88 R89 R90 R91 R92 R93 R94 R95 R96 R97 R98 R99 R100 R101 R102 R103: DIONEA_PACKAGE=0402
C6 C13 C20 C24 C61 C67 C72 C75: DIONEA_PACKAGE=0603
C19: DIONEA_PACKAGE=0805
C36 C44: library part KEMET_T52X_D_7343-31_DensityB, "KEMET T52X/T530 D case 7343-31; T2076 Table 2 Density Level B land and courtyard", DIONEA_PACKAGE=7343-31
D1 D2: library part Nexperia_PESD5V0S1UL_SOD882, "Nexperia PESD5V0S1UL SOD882; data sheet v5 2025-12-01 Figure 11 reflow footprint", DIONEA_PACKAGE=SOD882
D3 D5: library part PESD5V0C1BSF_SOD962-2, "Nexperia PESD5V0C1BSF, DSN0603-2 / SOD962-2; manufacturer reflow footprint, datasheet v3 2022-01-21", DIONEA_PACKAGE=SOD962-2
D4 D6 D7 D8 D9 D10 D11: library part TI_DYA0002A_SOD523, "TI DYA0002A 2-pin SOD-523; 4224978/B 09/2021 example board layout", DIONEA_PACKAGE=SOD-523_DYA
FB1 R62: DIONEA_PACKAGE=1206
FL1: library part Abracon_ABSES5AF_1109-5, "Abracon ABSES5AF-L100KM 1.1x0.9 mm 5-pad SAW; datasheet 2025-09-16 recommended land pattern", DIONEA_PACKAGE=1109-5
J6 J7: library part TE_2336582-1_NanoSIM, "TE Connectivity 2336582-1 Nano-SIM push-push H1.37; customer drawing C-2336582 Rev A2", DIONEA_PACKAGE=TE_NanoSIM_H1.37
J8 J9 J10: library part Hirose_U.FL-R-SMT-1, "Hirose U.FL-R-SMT-1 vertical receptacle; U.FL catalog 2026-08-01 recommended PCB and metal-mask patterns", DIONEA_PACKAGE=U.FL_SMT
J11: library part USB_C_Receptacle_GCT_USB4105-xx-A_16P_TopMnt_Horizontal, "USB 2.0 Type C Receptacle, GCT, 16P, top mounted, horizontal, 5A: https://gct.co/files/drawings/usb4105.pdf", DIONEA_PACKAGE=USB-C_16P_horizontal_top_mount_1.20mm_stake
J12: library part GCT_MEM2052-00-195-00-A, "GCT MEM2052-00-195-00-A microSD push-push connector; official drawing MEM2052 Rev A3, 2022-11-23", DIONEA_PACKAGE=microSD_push-push_1.95mm_8P_CD
J13: library part Molex_504050-0291_PicoLock-2, "Molex 504050-0291 Pico-Lock 1.50 mm two-circuit right-angle SMT; customer drawing 5040500000-SD PSD 001 Rev B", DIONEA_PACKAGE=Pico-Lock_1.5mm_2P_RA_SMT
J_MIC1 J_MIC2 J_MIC3 J_MIC4: library part Molex_Pico-Lock_504050-0691_1x06-1MP_P1.50mm_Horizontal, "Molex Pico-Lock series connector, 504050-0691 (http://www.molex.com/pdm_docs/sd/5040500891_sd.pdf), generated with kicad-footprint-generator", DIONEA_PACKAGE=Pico-Lock_1.5_1x06_Right_Angle
J_PWR: library part Molex_43045-1202_MicroFit-12_RA, "Molex 43045-1202 Micro-Fit 3.0 2x6 right-angle through-hole; customer drawing SD-43045-001 PSD 001 Rev H1", DIONEA_PACKAGE=Micro-Fit_3.0_2x06_Right_Angle
L1: DIONEA_PACKAGE=1210
Q1 Q2 Q3: library part Nexperia_MMBT3904_SOT23, "Nexperia MMBT3904 SOT23; data sheet v5 2026-04-08 Figure 8 reflow footprint", DIONEA_PACKAGE=SOT23
Q4: library part Vishay_Si1016X_SC-89, "Vishay Si1016X SC-89 6-lead; Application Note 826 recommended minimum pads", DIONEA_PACKAGE=SOT-563_SC-89
TP_BLE_SWD TP_CELL_USB: DIONEA_PACKAGE=POGO_FIXTURE_4P
TP_CELL_DBG TP_MCU_SWD: DIONEA_PACKAGE=POGO_FIXTURE_5P
TP_EOL: DIONEA_PACKAGE=POGO_FIXTURE_13P
U1: library part ST_STM32U585_LQFP100_1L, "ST STM32U585 LQFP100 package 1L; DS13086 Rev 10 Figure 96 footprint example", DIONEA_PACKAGE=LQFP100_14x14
U2: library part Winbond_W25Q512JV_PackageF_IPC_Candidate, "Winbond W25Q512JV package F SOIC-16 300 mil; project-controlled KiCad IPC gullwing candidate; assembler DFM required", DIONEA_PACKAGE=SOIC-16_300mil_F
U3: library part ST_LIS2DW12_LGA-12L, "ST LIS2DW12 LGA-12L; DS11811 Rev 9 package geometry and TN0018 Rev 8 PCB/stencil rules", DIONEA_PACKAGE=LGA-12_2x2mm
U4: library part STTS22H_UDFN-6L, "ST STTS22H UDFN-6L 2x2 mm; DS12606 Rev8 Figures 10 and 11", DIONEA_PACKAGE=UDFN-6L_2x2mm
U5: library part LT6000_DCB-7, "Analog Devices LT6000 DCB 6-lead DFN 2x3 mm; LTC DWG 05-08-1715", DIONEA_PACKAGE=DFN-6_DCB_2x3mm
U6: library part TI_DBV0005A_SOT23-5, "TI DBV0005A 5-pin SOT-23; 4214839/K 08/2024 example board layout", DIONEA_PACKAGE=SOT-23-5_DBV
U7 U13 U16: library part TI_PW0024A_TSSOP24, "TI PW0024A 24-pin TSSOP; 4220208/A 02/2017 example board layout", DIONEA_PACKAGE=TSSOP-24_PW
U8: library part Quectel_BG95-M3_LGA-102, "Quectel BG95-M3 LGA-102; recommended footprint in BG95 Series Hardware Design V1.8 Figure 46", DIONEA_PACKAGE=LGA-102_23.6x19.9mm
U9: library part u-blox_MAX-M10S_LCC-18, "u-blox MAX-M10S LCC-18; UBX-20053088 R05 Figure 30 and Table 44 copper/mask pattern", DIONEA_PACKAGE=LCC-18_9.7x10.1mm
U10: library part Ebyte_E22-M22S_Castellated-22, "Ebyte E22-170/400/900M22S 14x20 mm castellated module; user manual v1.2 section 3.2 bottom-pad pattern", DIONEA_PACKAGE=SMD_20x14_22P_1.27mm
U11: library part Raytac_MDBT50Q-P1MV2, "Raytac MDBT50Q-P1MV2; Footprint Design Guide 230606 solder-pad and RF-layout control", DIONEA_PACKAGE=nRF52840_SMD_10.5x15.5_61P_PCB_antenna
U14 U15: library part ST_ESDALC6V1-5P6_SOT666, "ST ESDALC6V1-5P6 SOT666; data sheet Rev 3 Figure 14 footprint", DIONEA_PACKAGE=SOT666_1.6x1.6mm
U17: library part TI_PW0014A_TSSOP14, "TI PW0014A 14-pin TSSOP; 4220202/B 12/2023 example board layout", DIONEA_PACKAGE=TSSOP-14_PW
U18: library part TI_DRL0006A_SOT6, "TI DRL0006A 6-pin SOT-5X3; 4223266/F 11/2024 example board layout", DIONEA_PACKAGE=SOT-5X3-6_DRL
U19 U20 U21 U22 U23 U24 U27: library part TI_DQA0010A_USON10, "TI DQA0010A 10-pin USON; 4220328/A 12/2015 example board layout", DIONEA_PACKAGE=USON-10_DQA
U25 U26: library part TI_DRT0003A_IPC_Candidate, "TI DRT0003A 3-pin SOT-9X3; project-controlled KiCad package-derived candidate; assembler DFM and USB SI review required", DIONEA_PACKAGE=SOT-9X3_DRT
X1: library part SiT1552_JE_CSP-4, "SiTime SiT1552 JE 4LD 1.54x0.84 mm CSP; POD-35 Rev A recommended land pattern", DIONEA_PACKAGE=CSP-4_1.5x0.8mm

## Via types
v1: diameter 0.5, hole 0.3, F.Cu to B.Cu, tented both sides, 579 vias
v2: diameter 0.25, hole 0.15, F.Cu to B.Cu, tented both sides, 274 vias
